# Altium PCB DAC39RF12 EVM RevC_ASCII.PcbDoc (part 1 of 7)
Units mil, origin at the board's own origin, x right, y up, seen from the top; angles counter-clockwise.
Board outline 5071.81 x 2716.54 mil, 16 copper layers (Top Layer, L2 GND1, L3 PWR1, L4 GND2, L5 PWR2, L6 GND3, L7 Ctrl Signal 1, L8 GND4, L9 GND5, L10 Ctrl Signal 2, L11 GND6, L12 PWR3, L13 GND7, L14 PWR4, L15 GND8, Bottom Layer), stack 82.4 mil thick; 596 components, 375 nets, 3310 pads, 1662 vias.
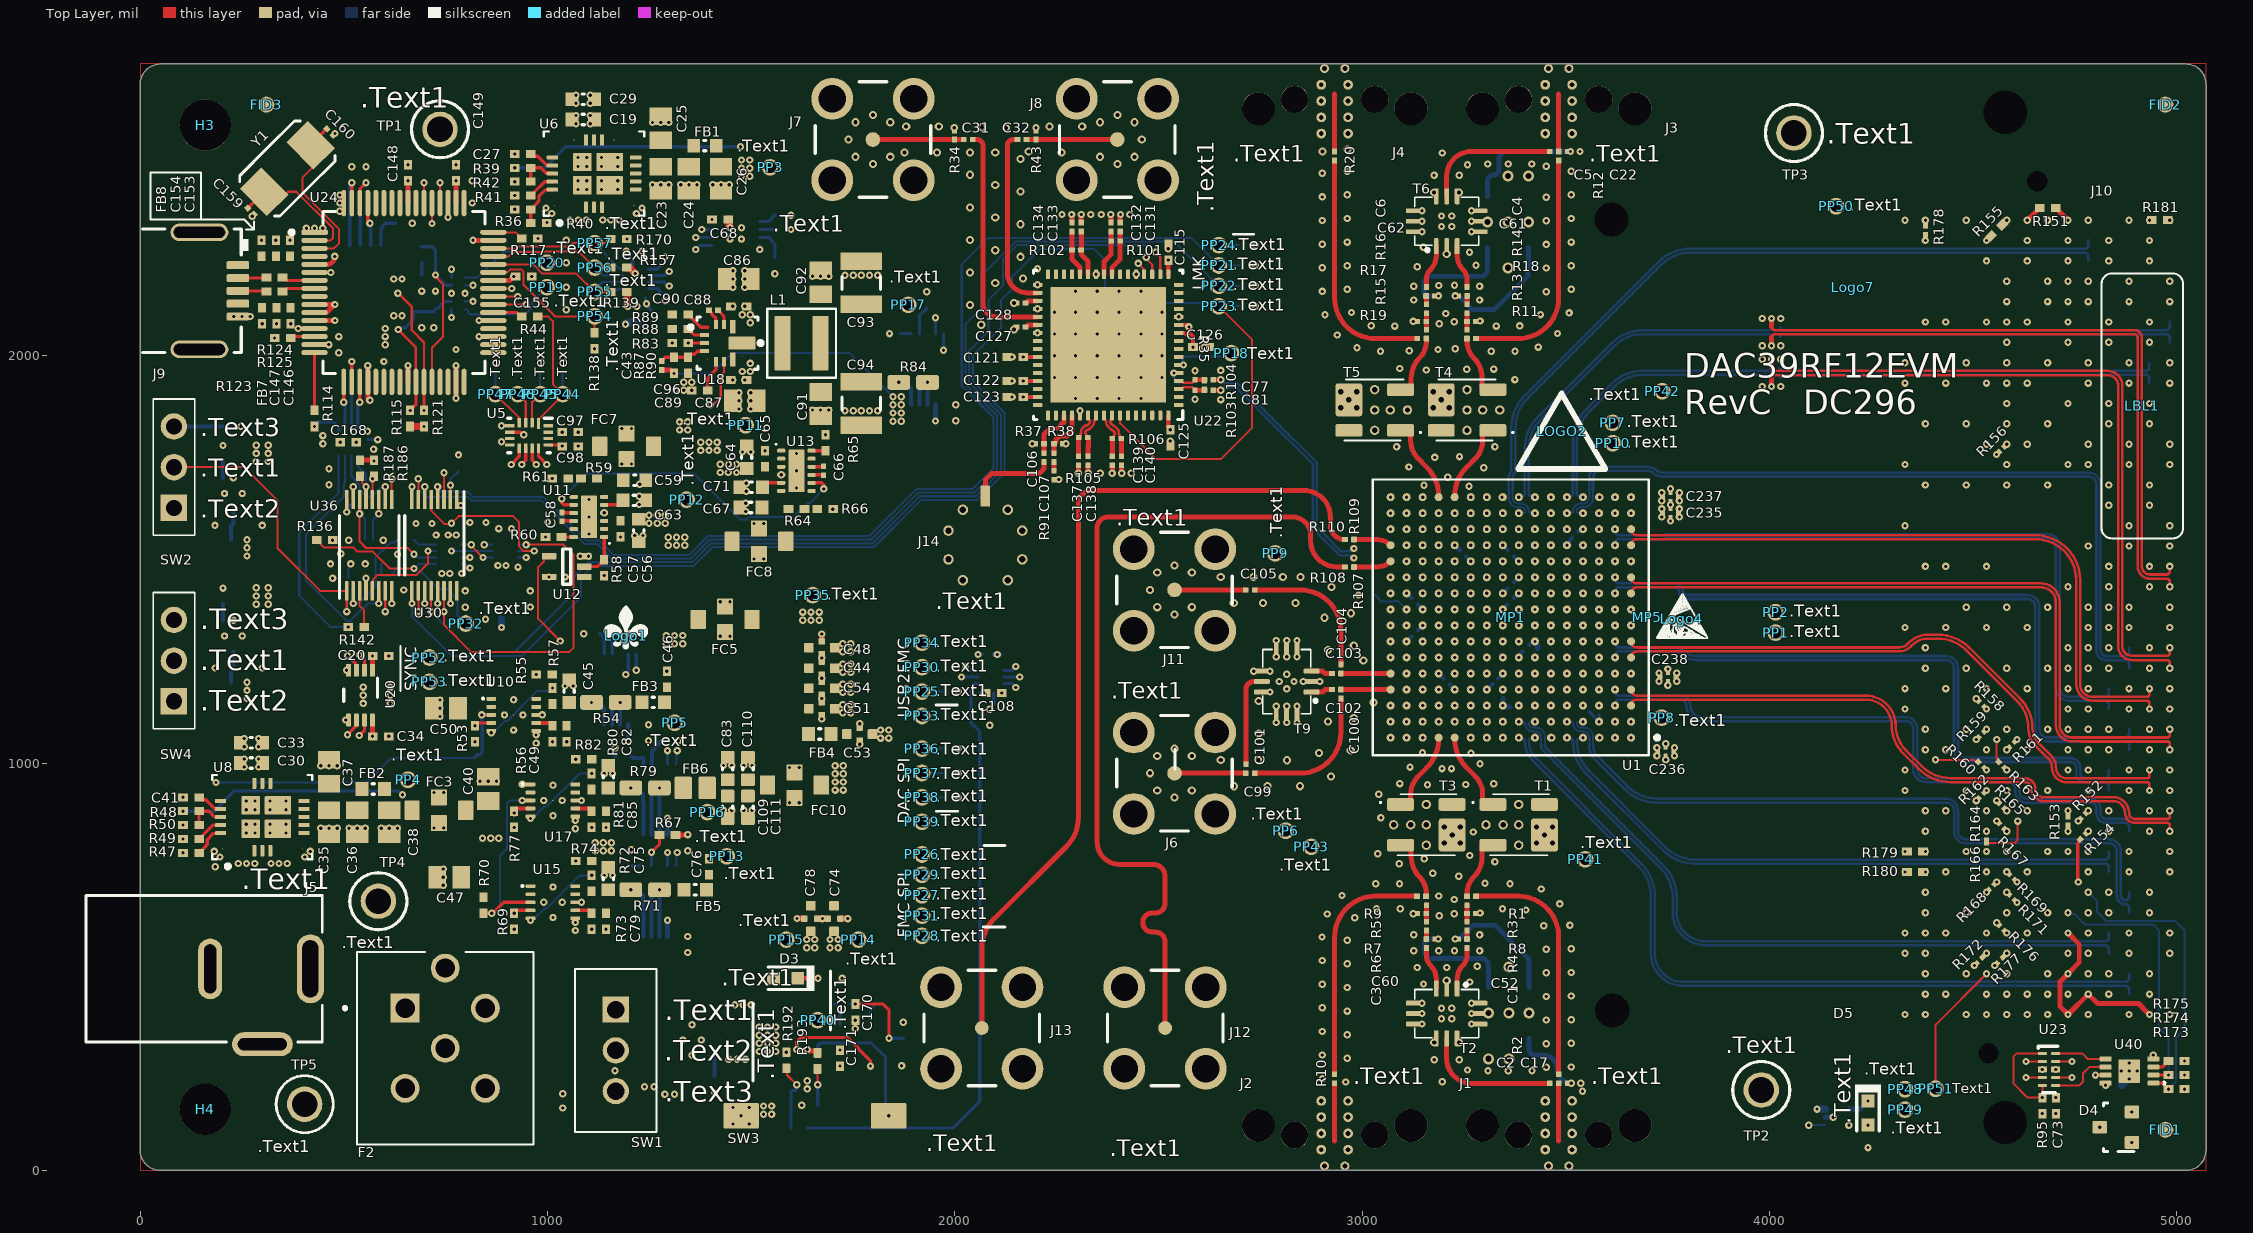
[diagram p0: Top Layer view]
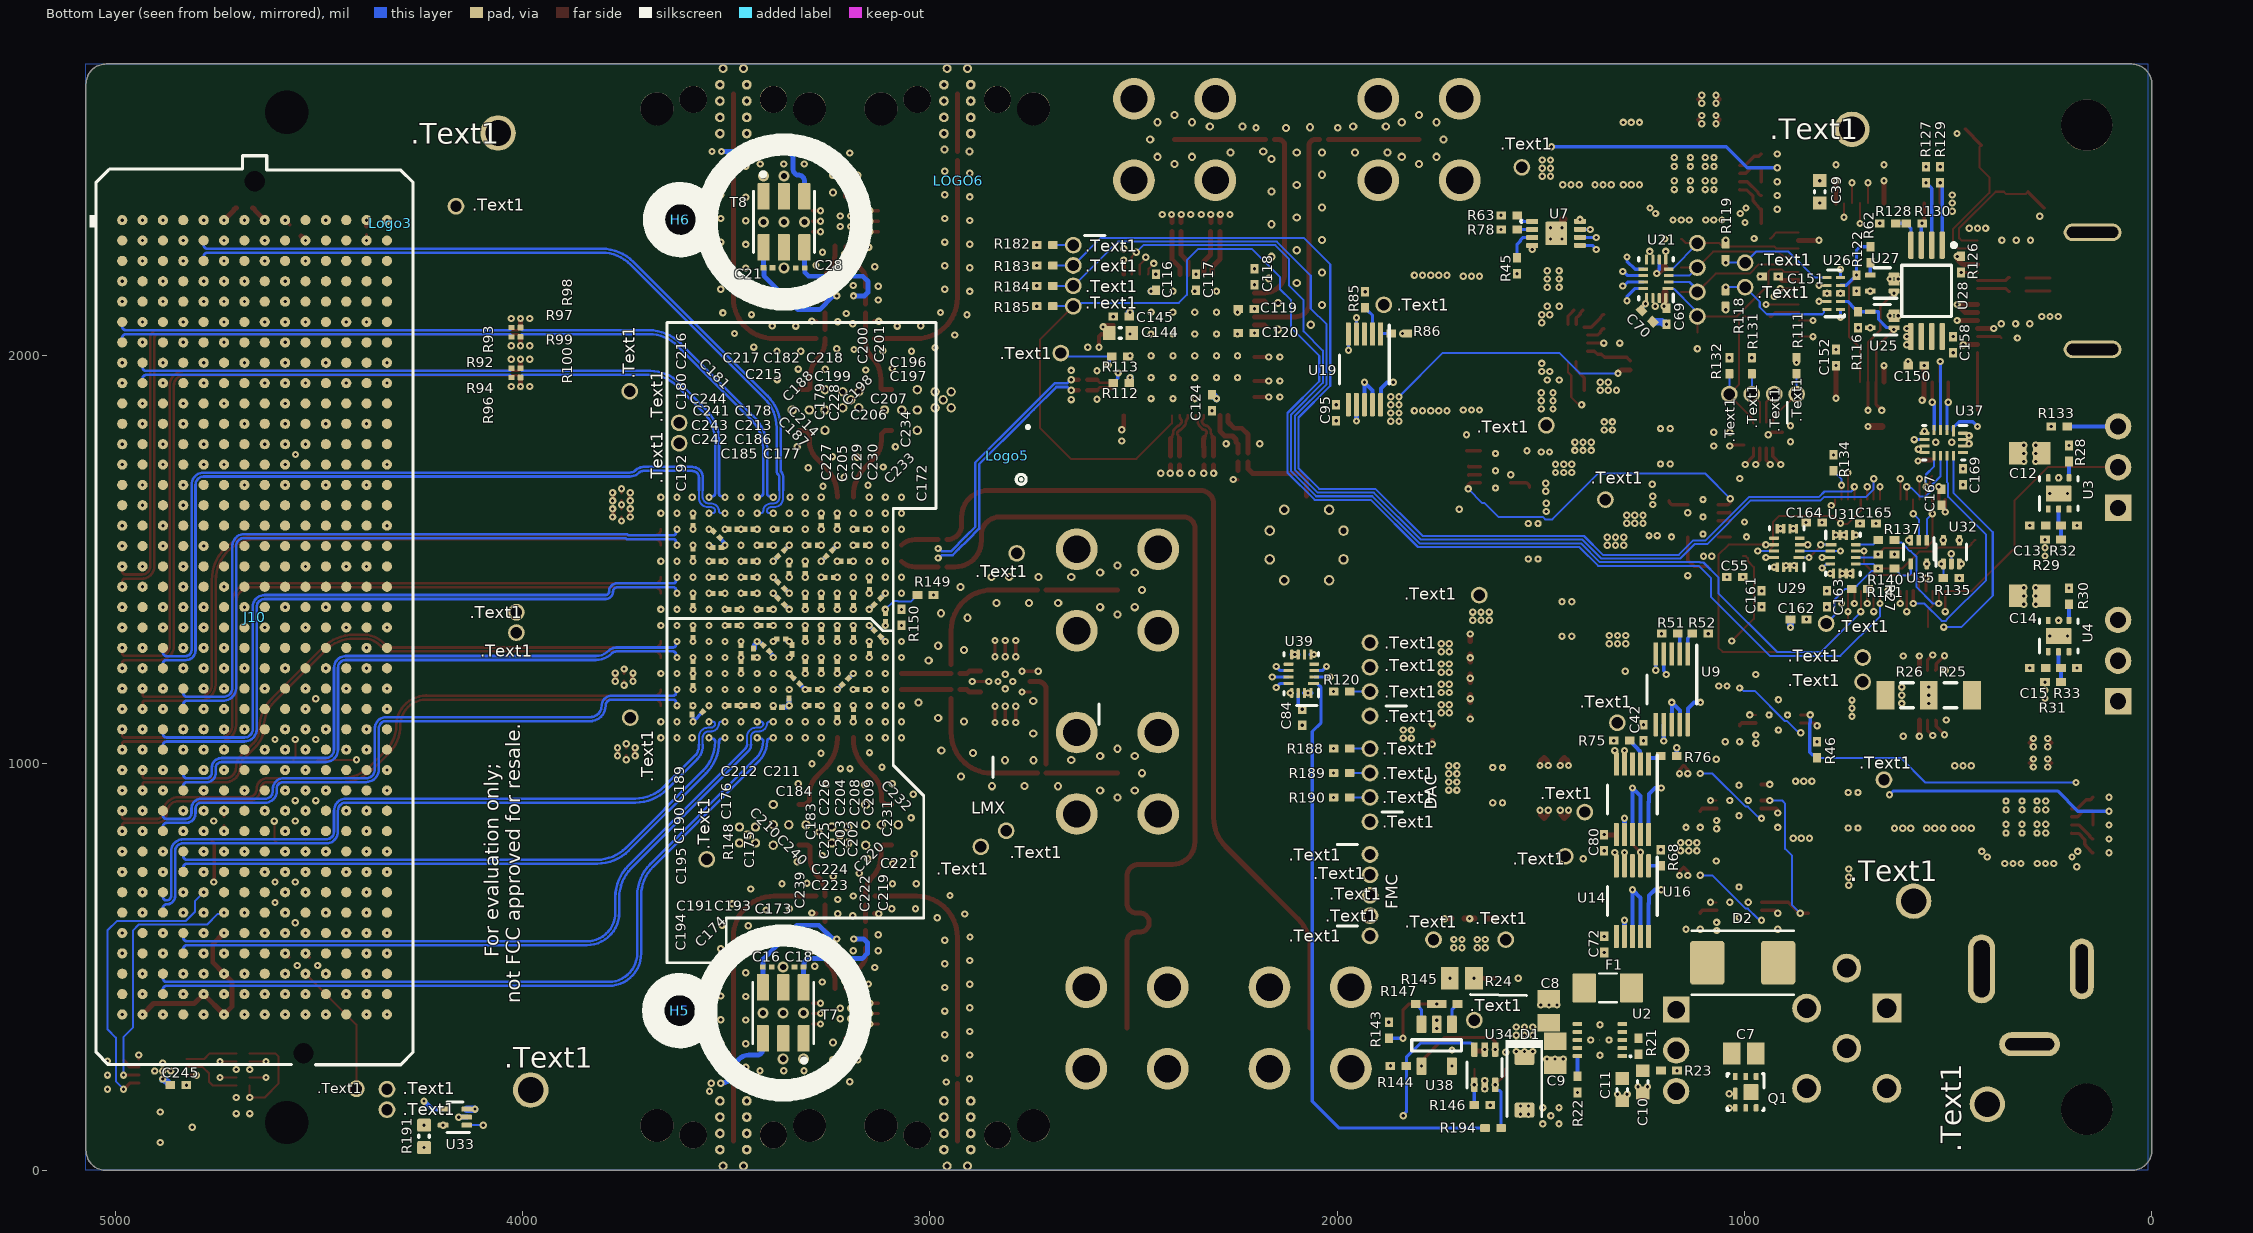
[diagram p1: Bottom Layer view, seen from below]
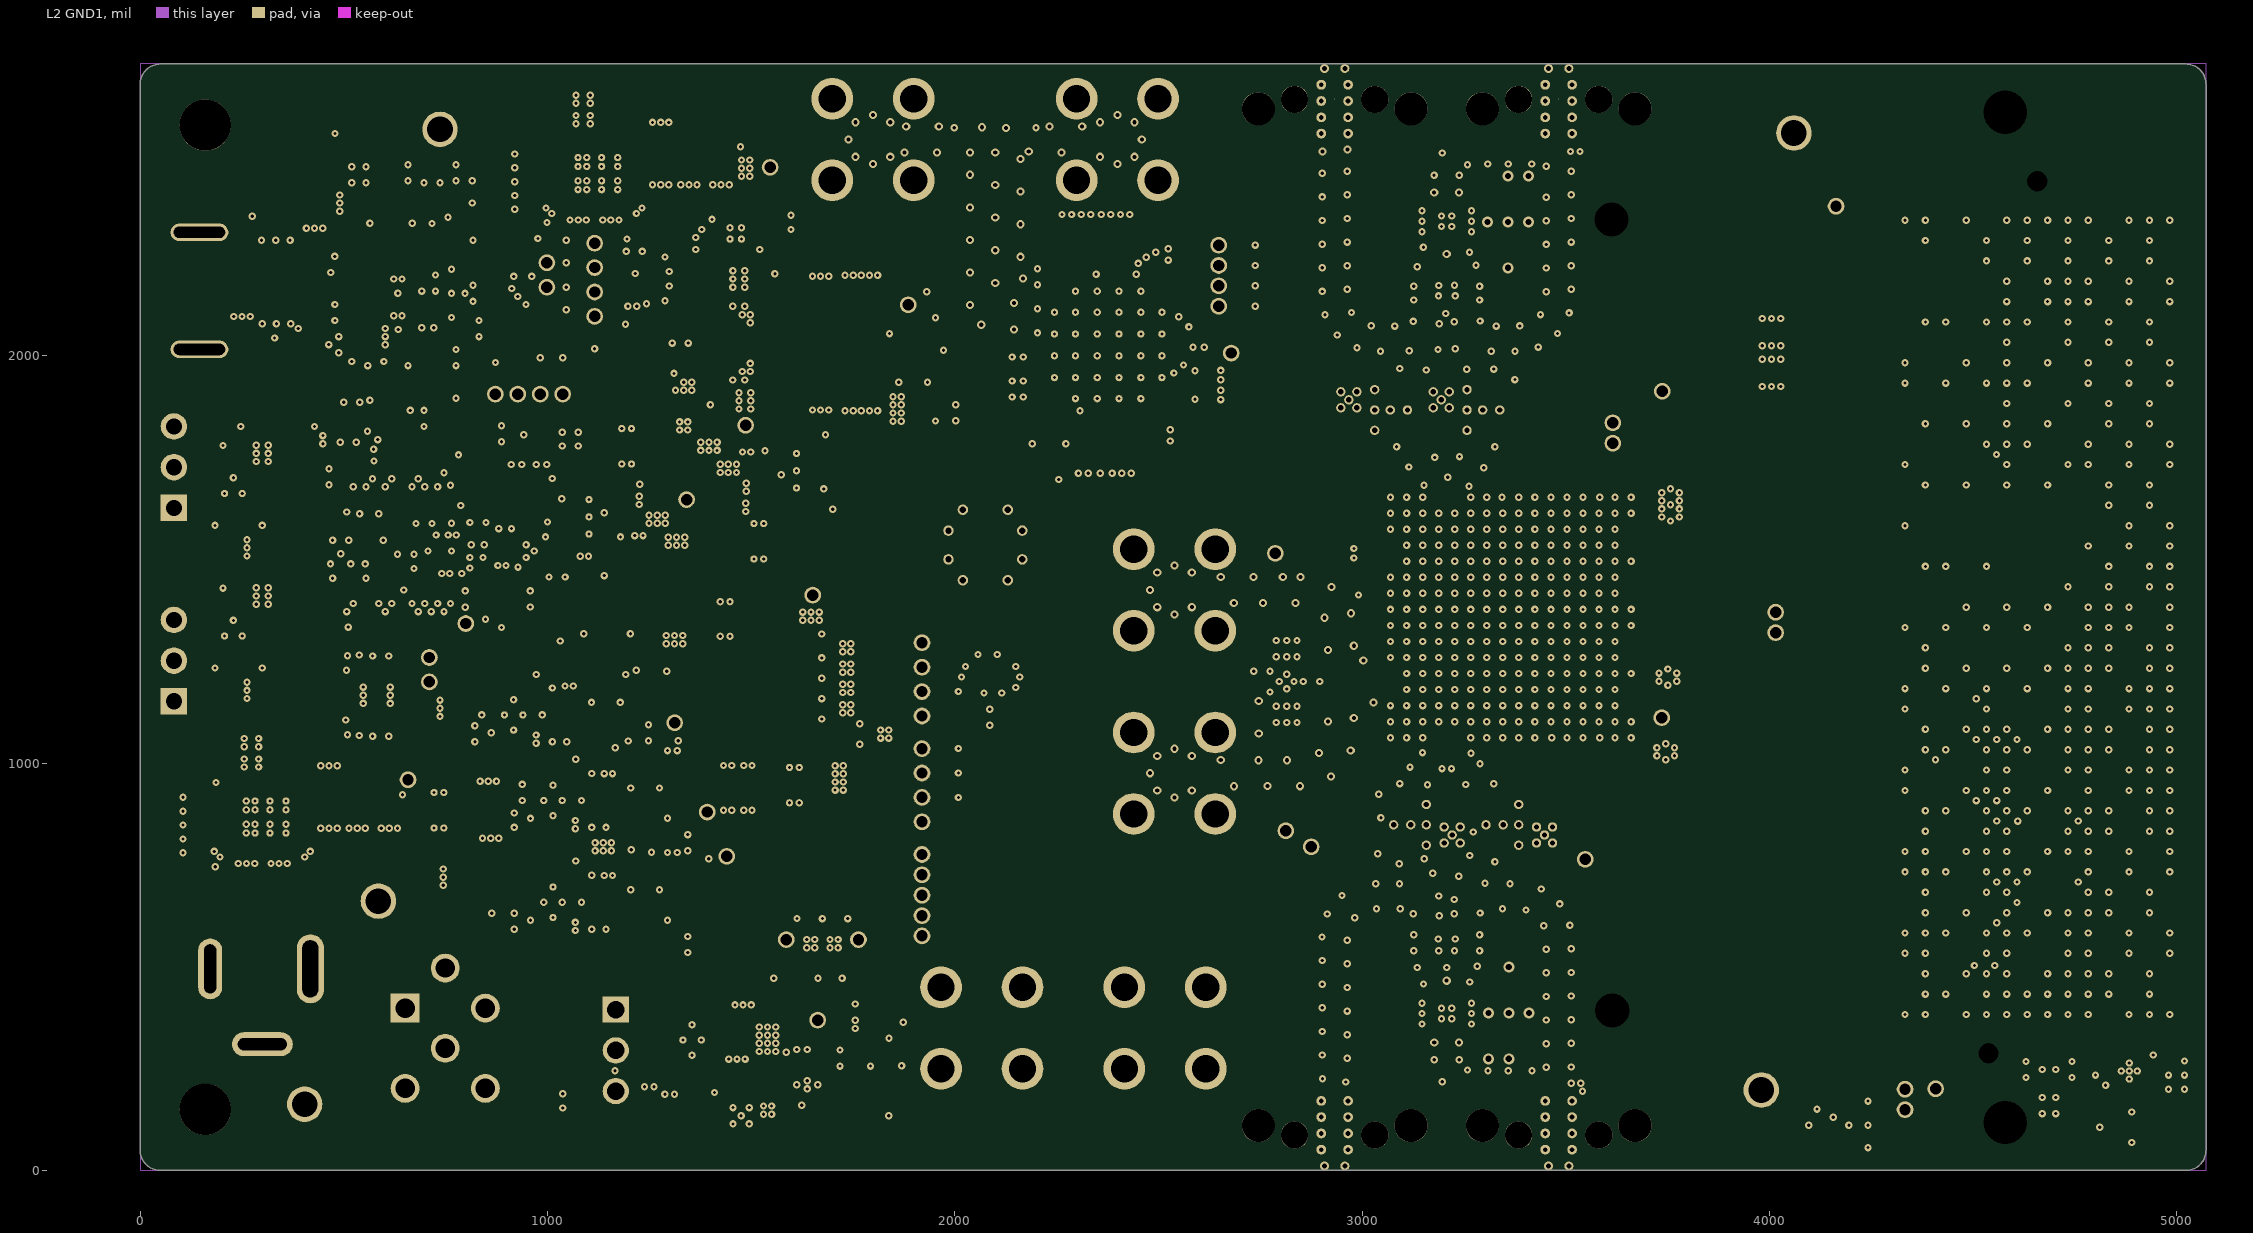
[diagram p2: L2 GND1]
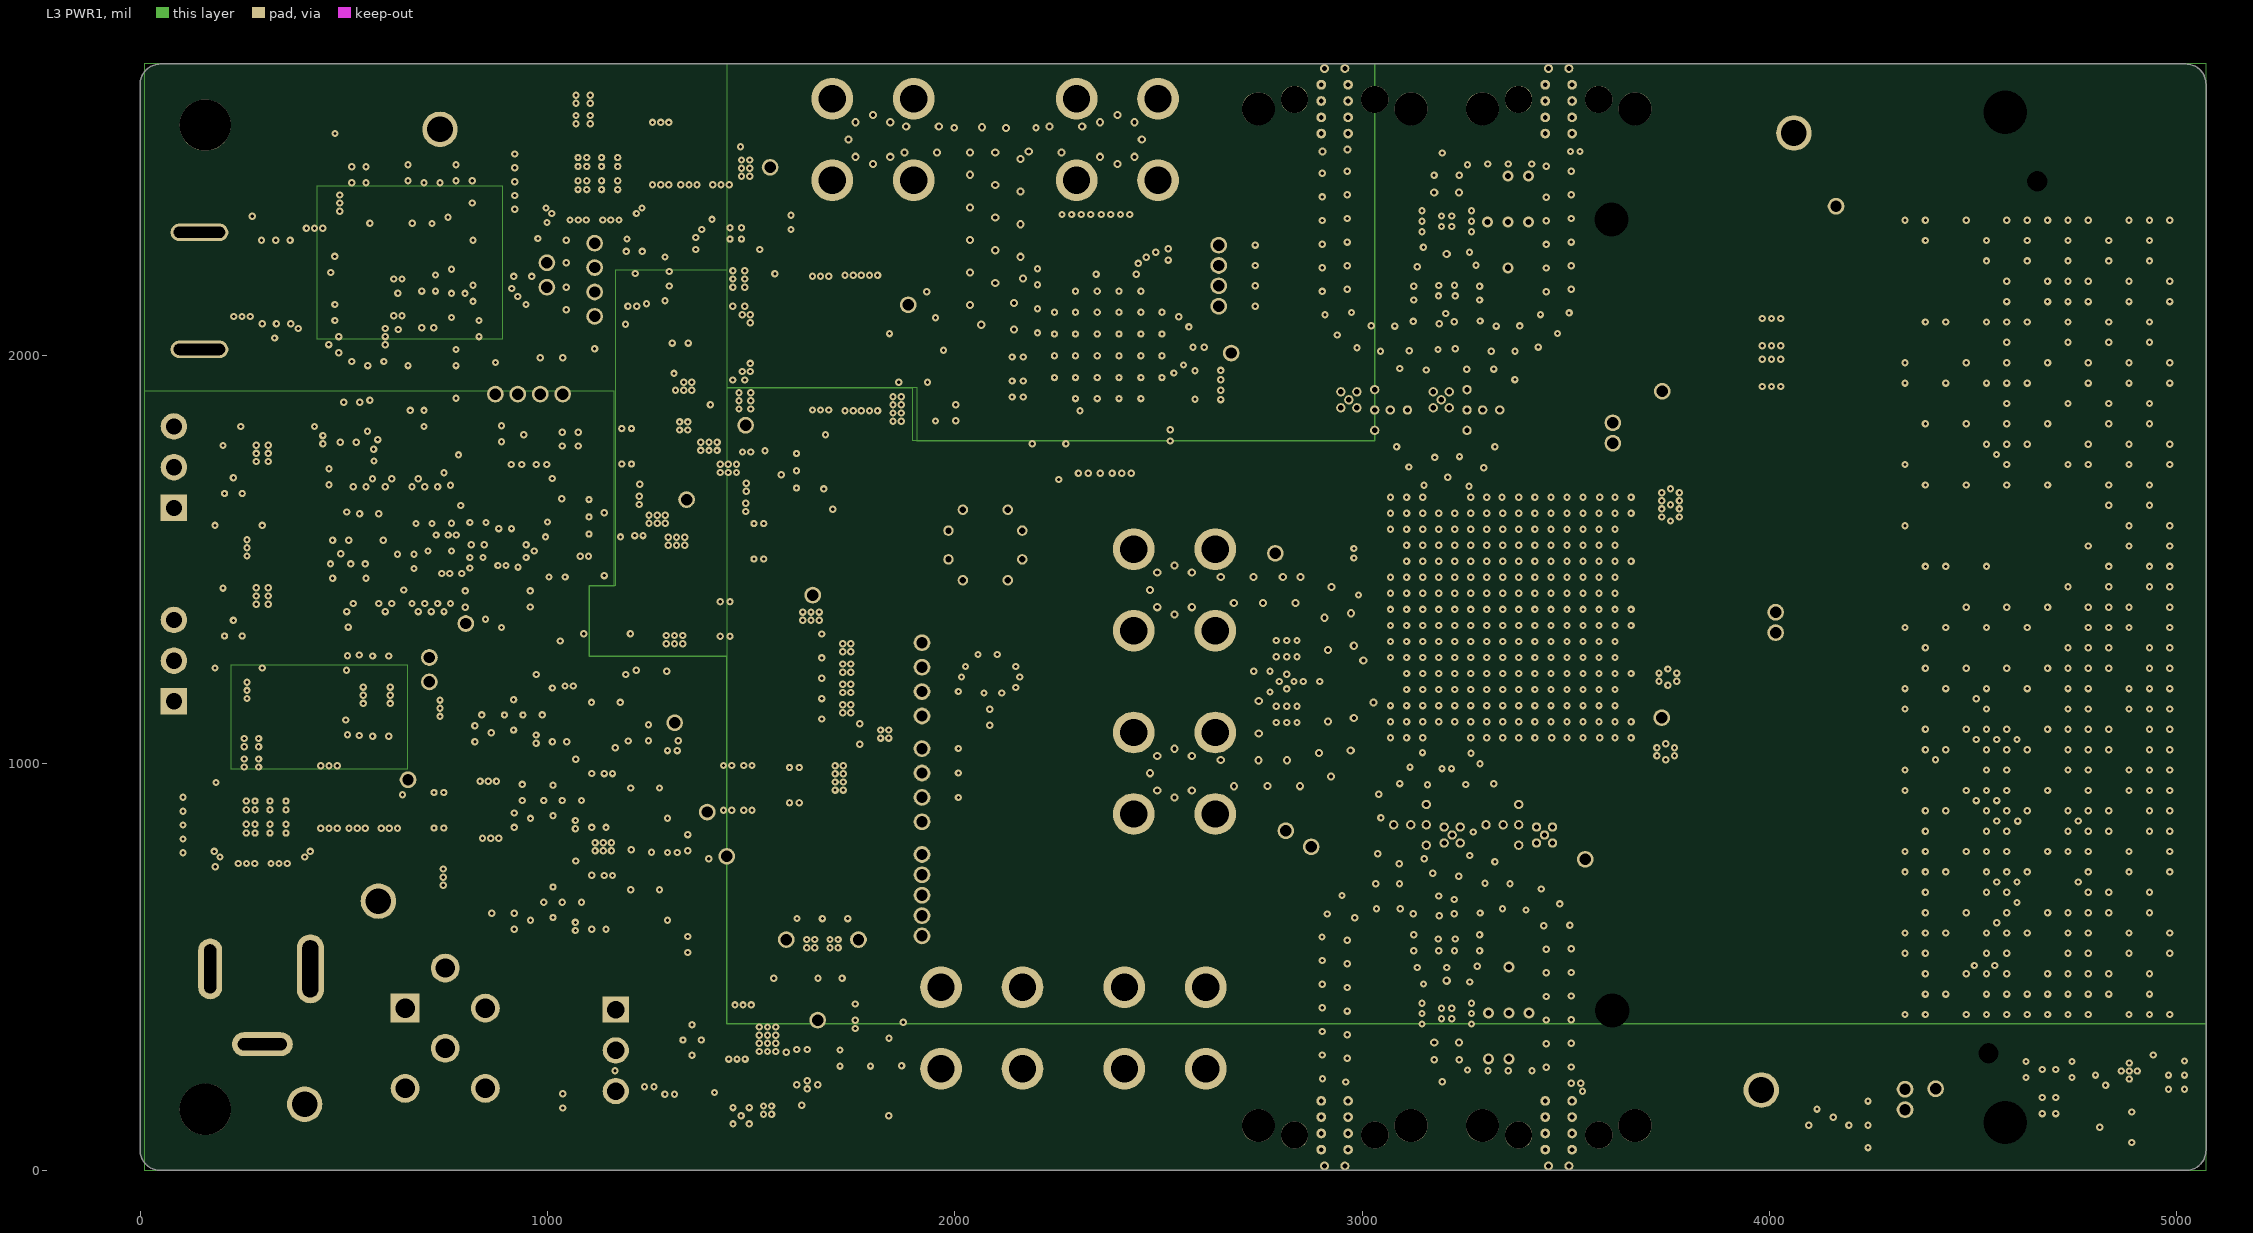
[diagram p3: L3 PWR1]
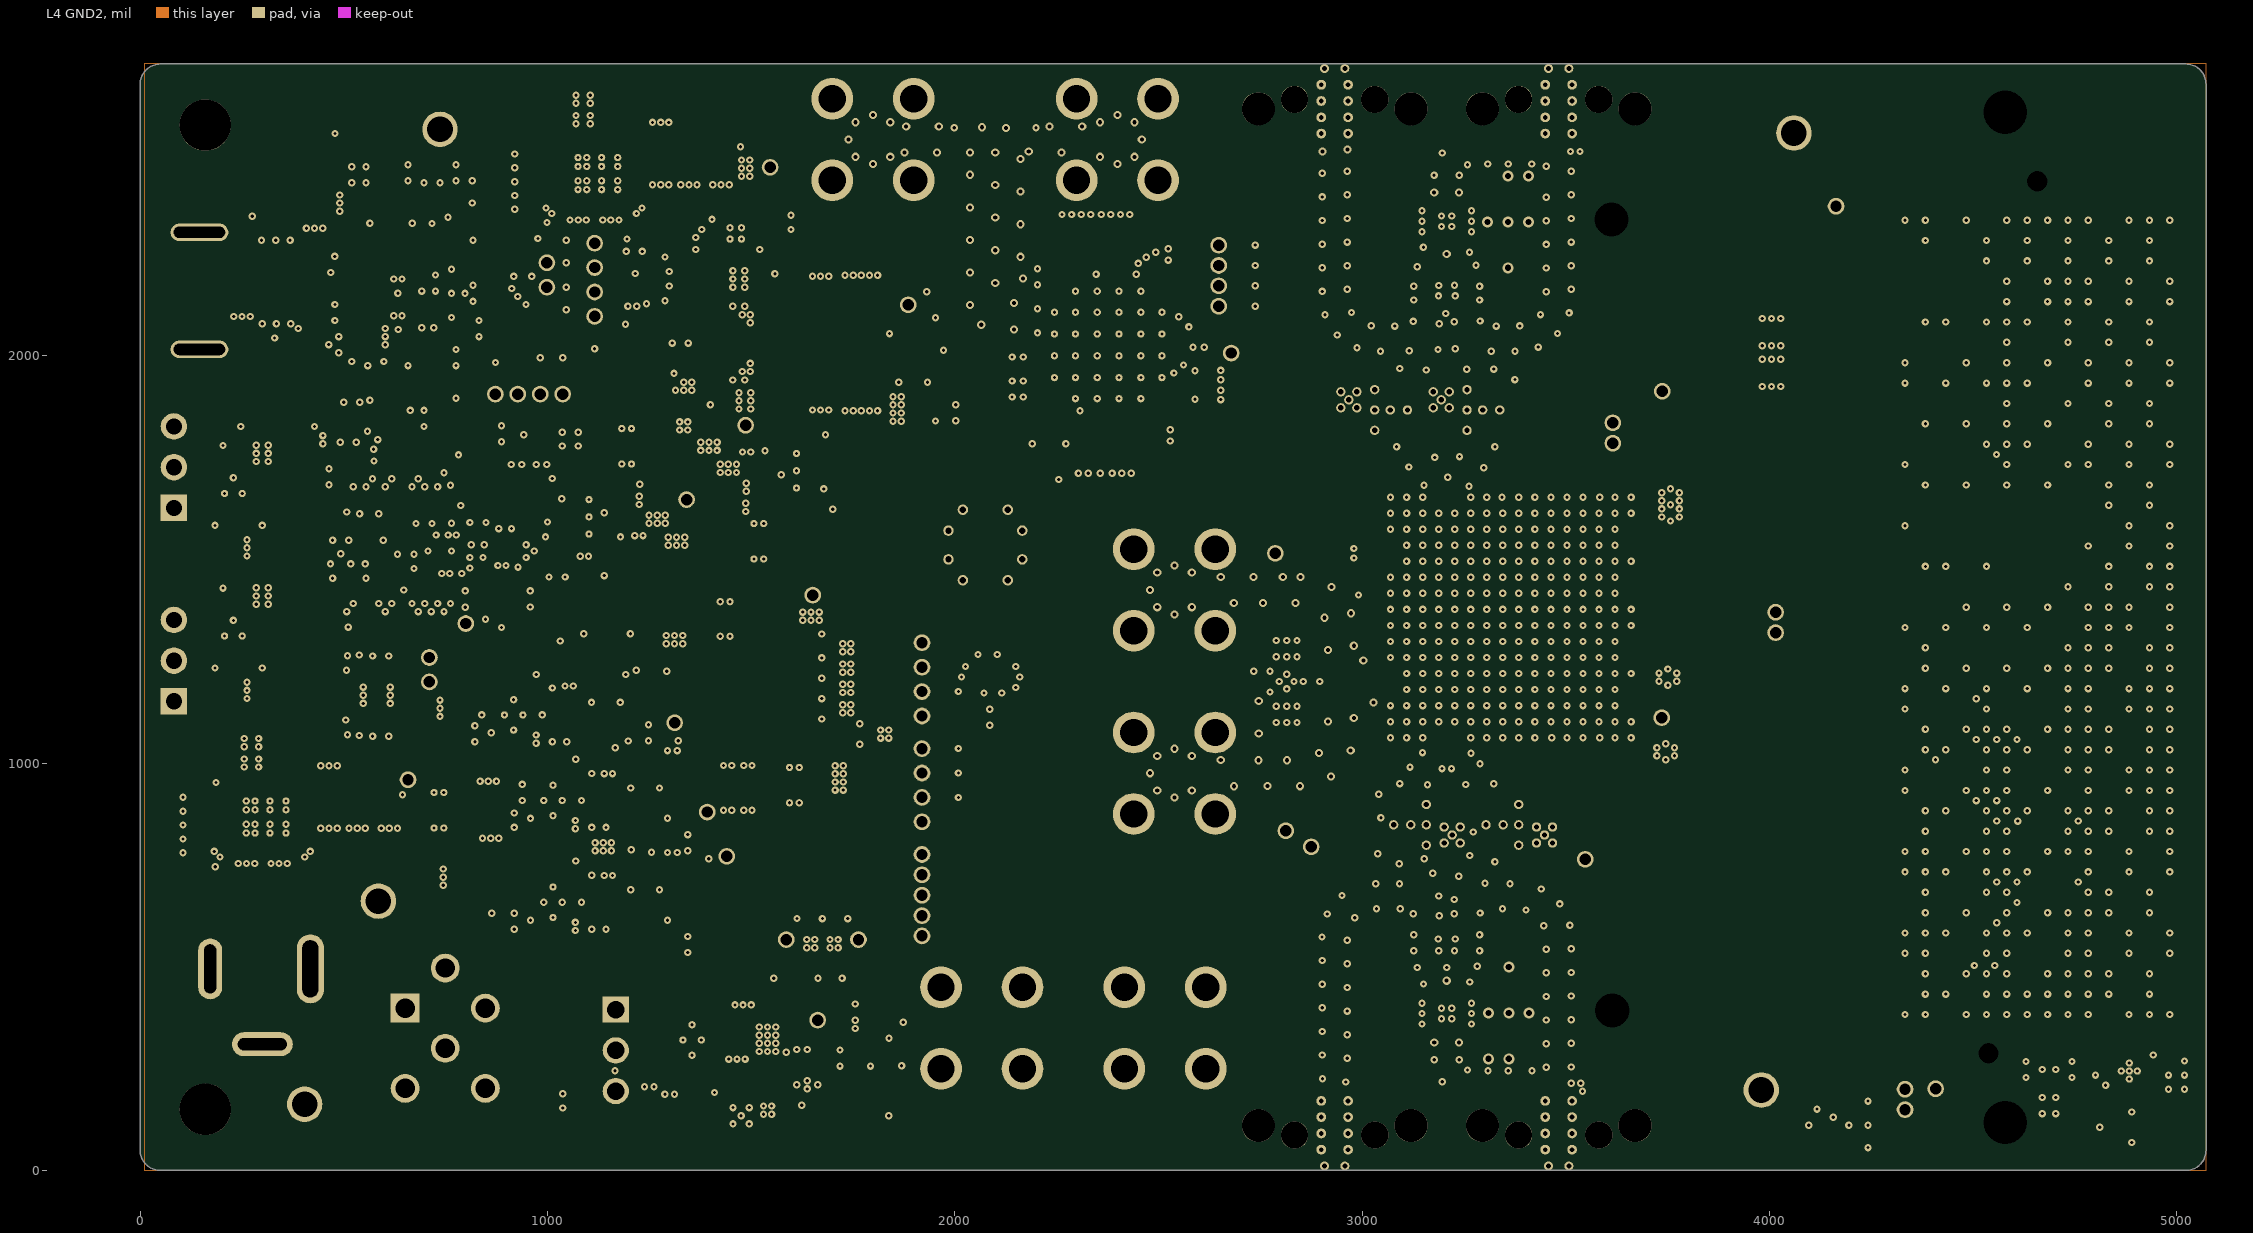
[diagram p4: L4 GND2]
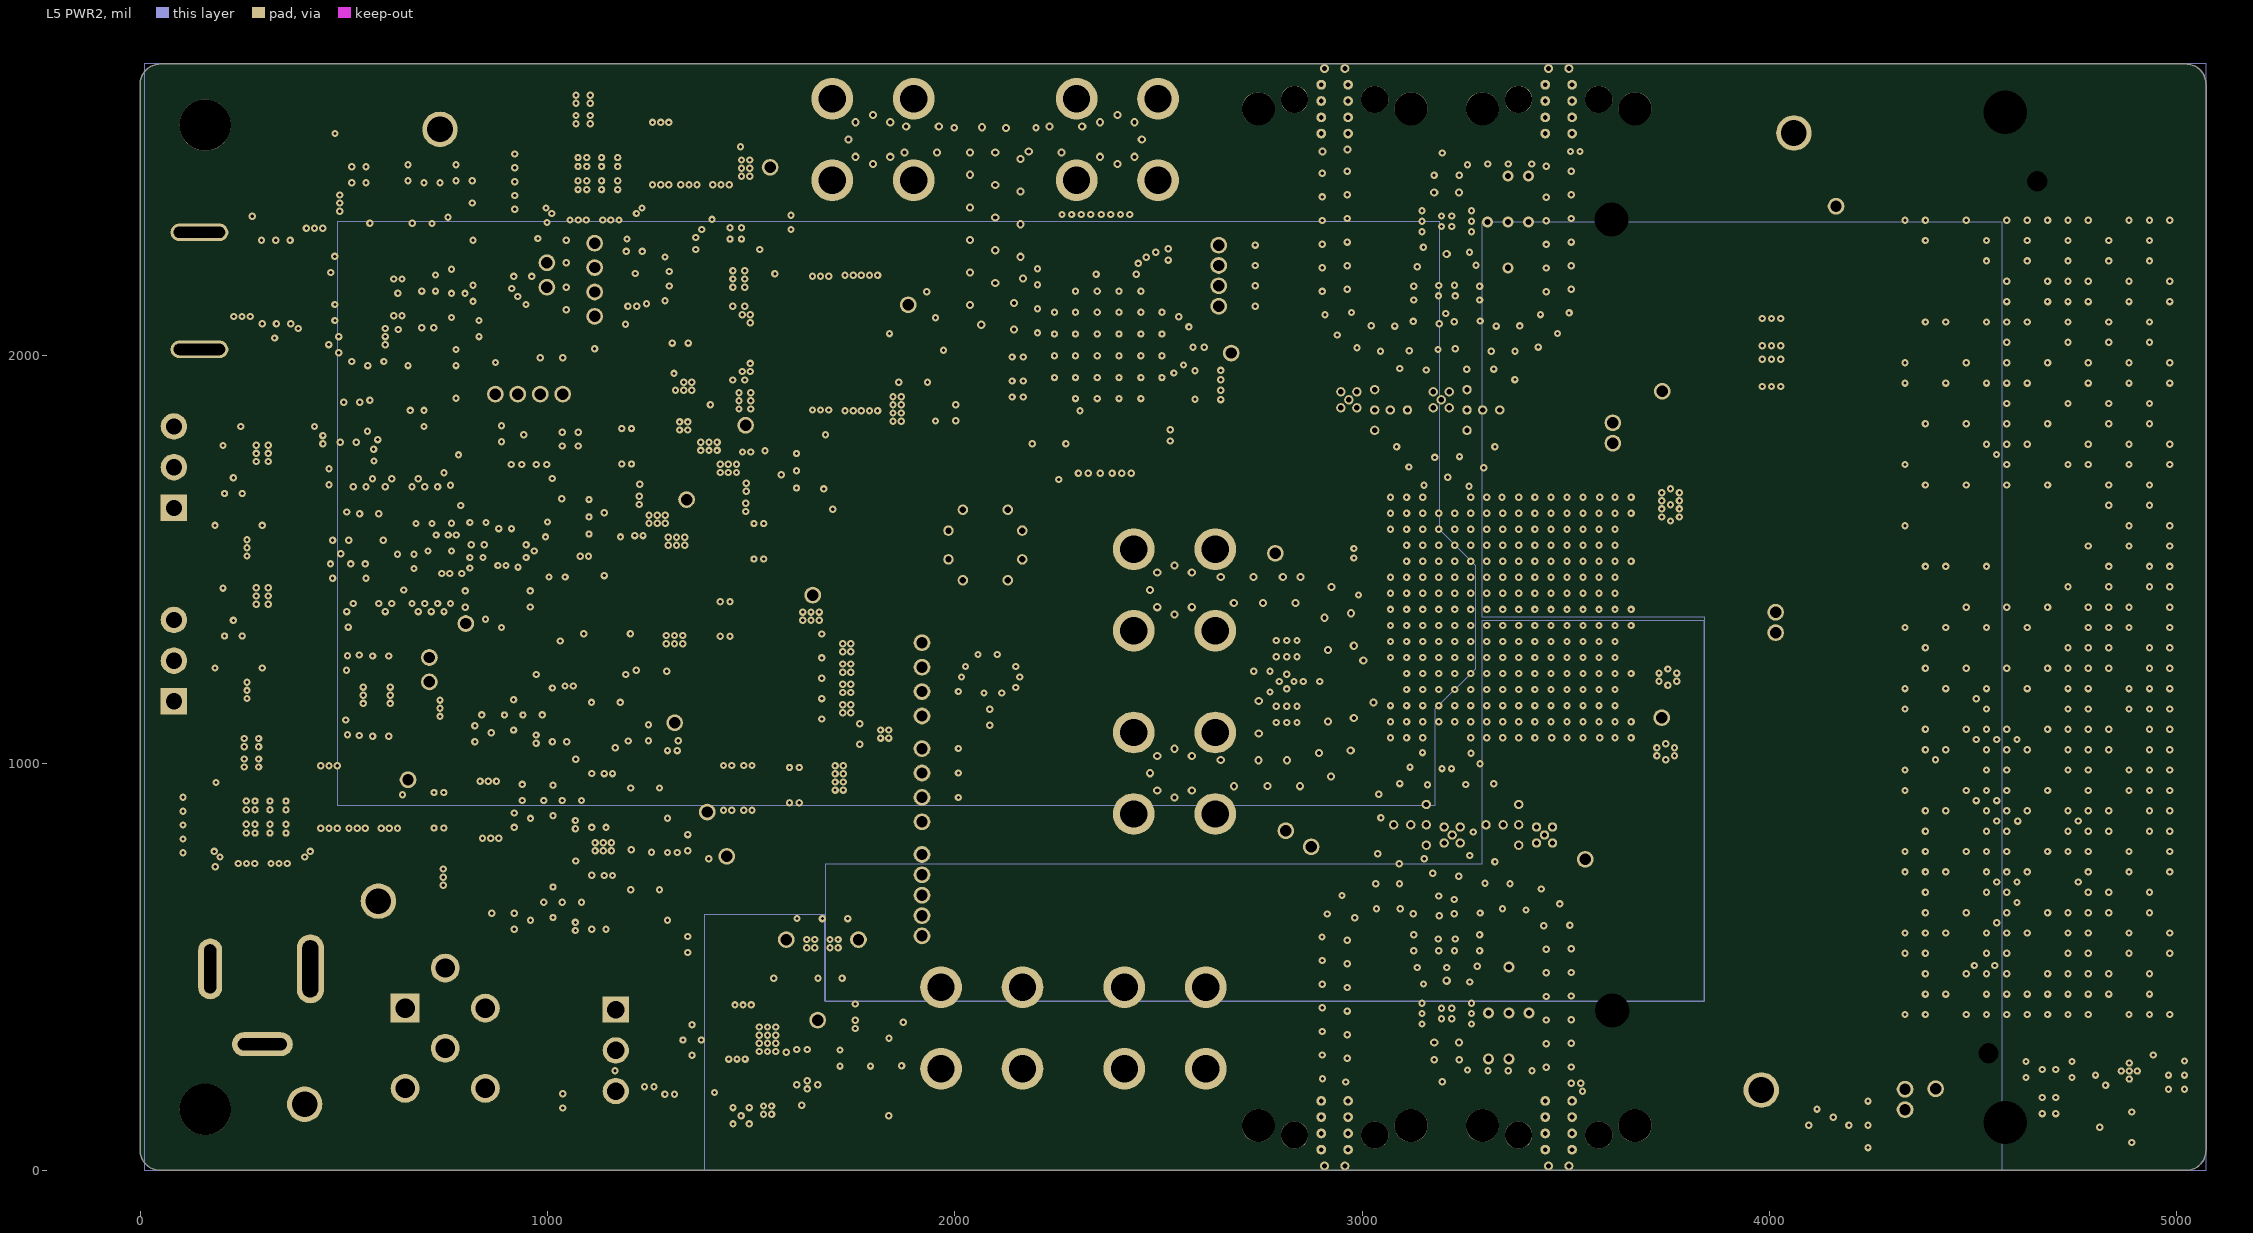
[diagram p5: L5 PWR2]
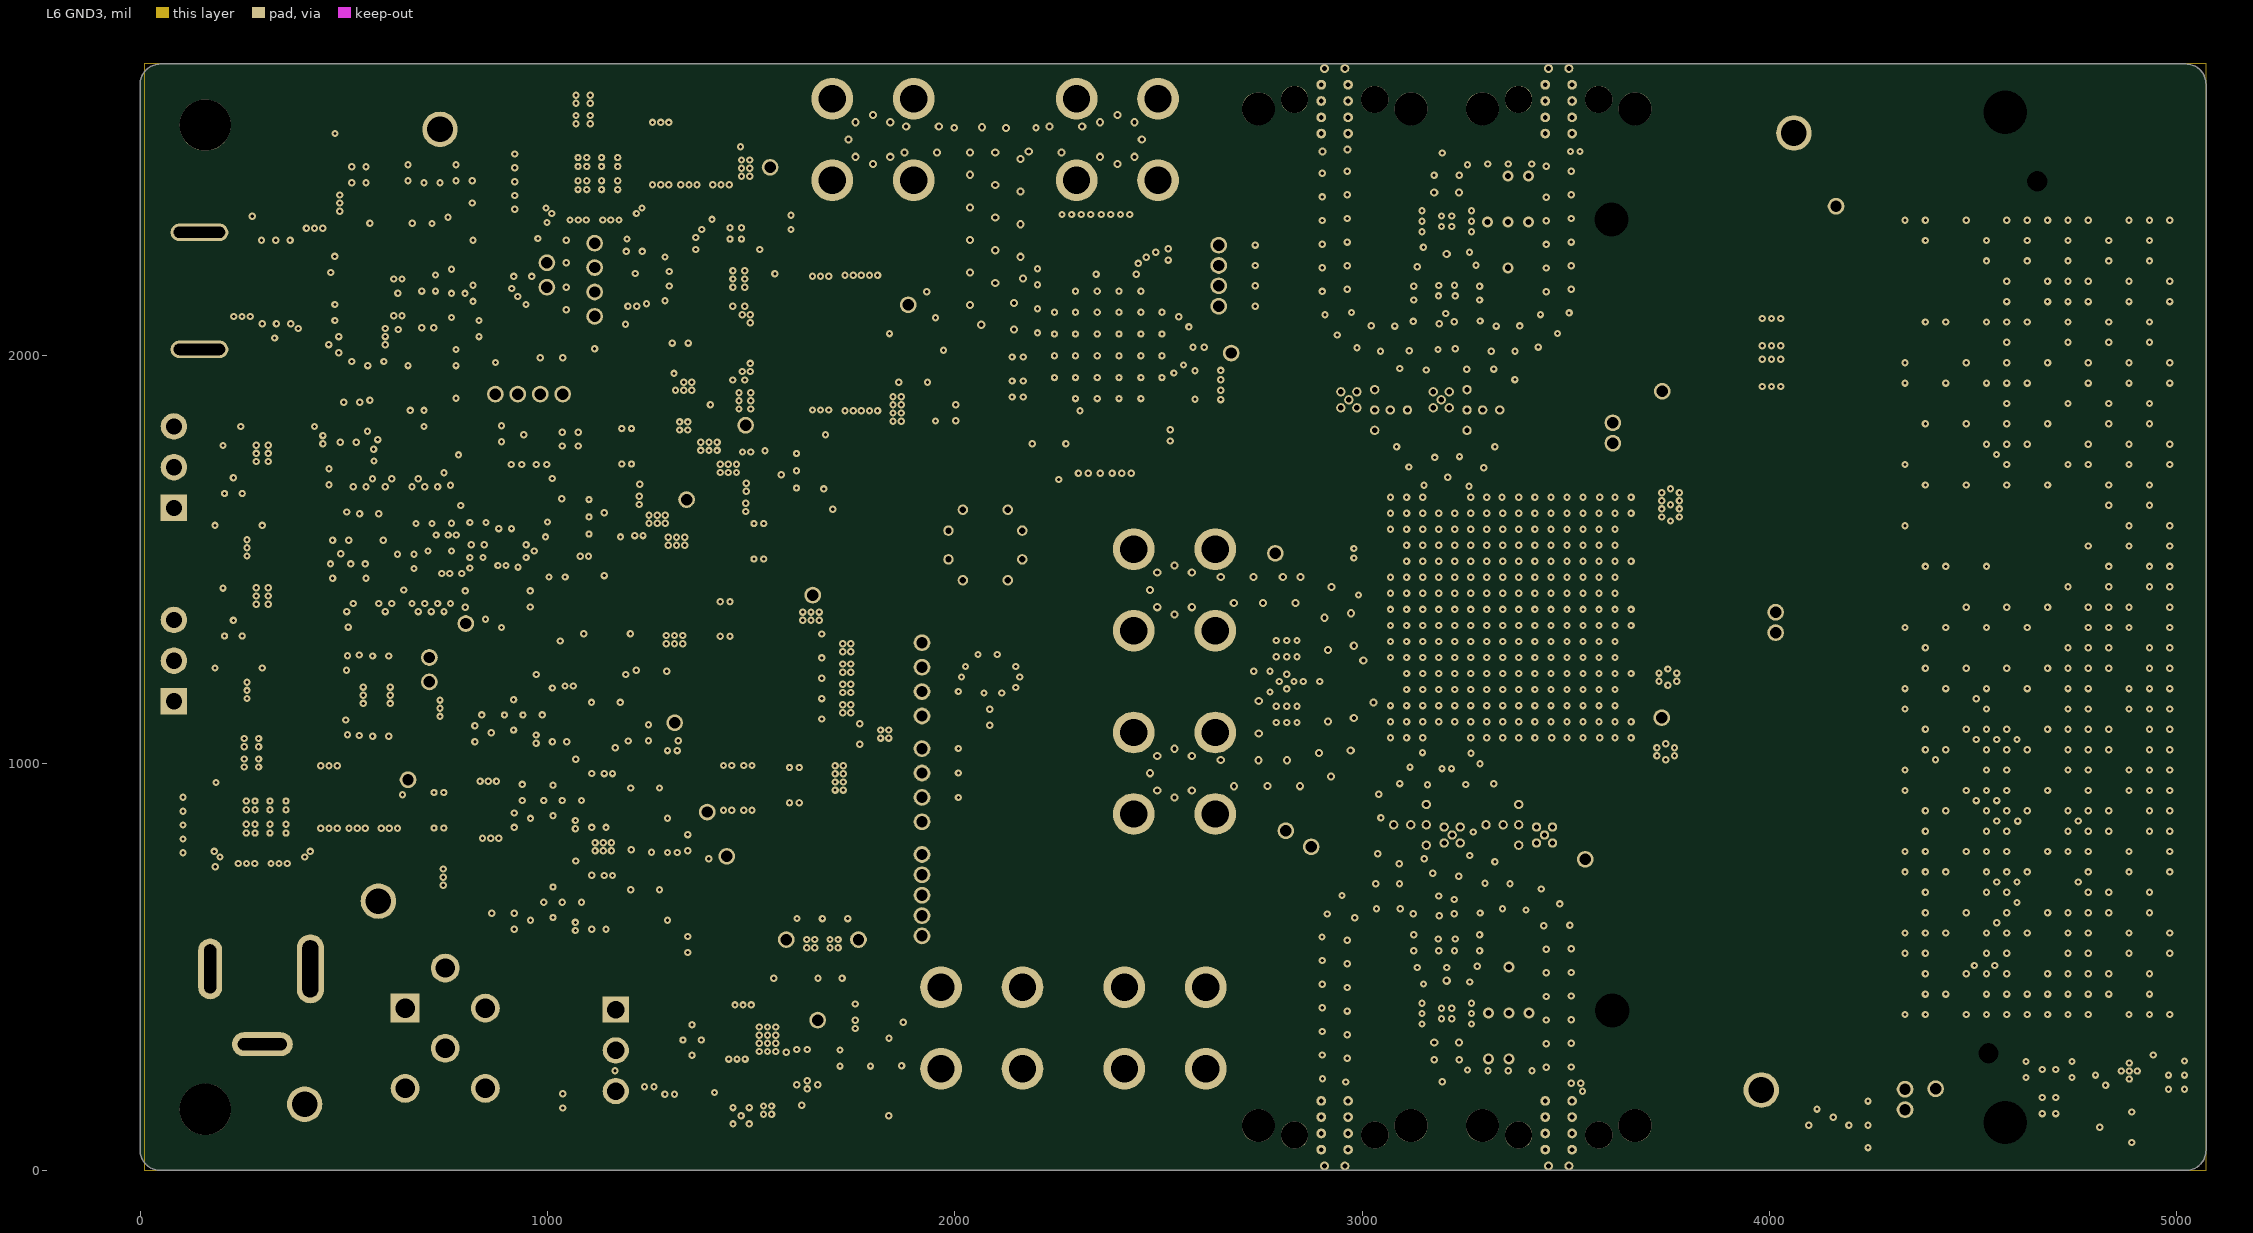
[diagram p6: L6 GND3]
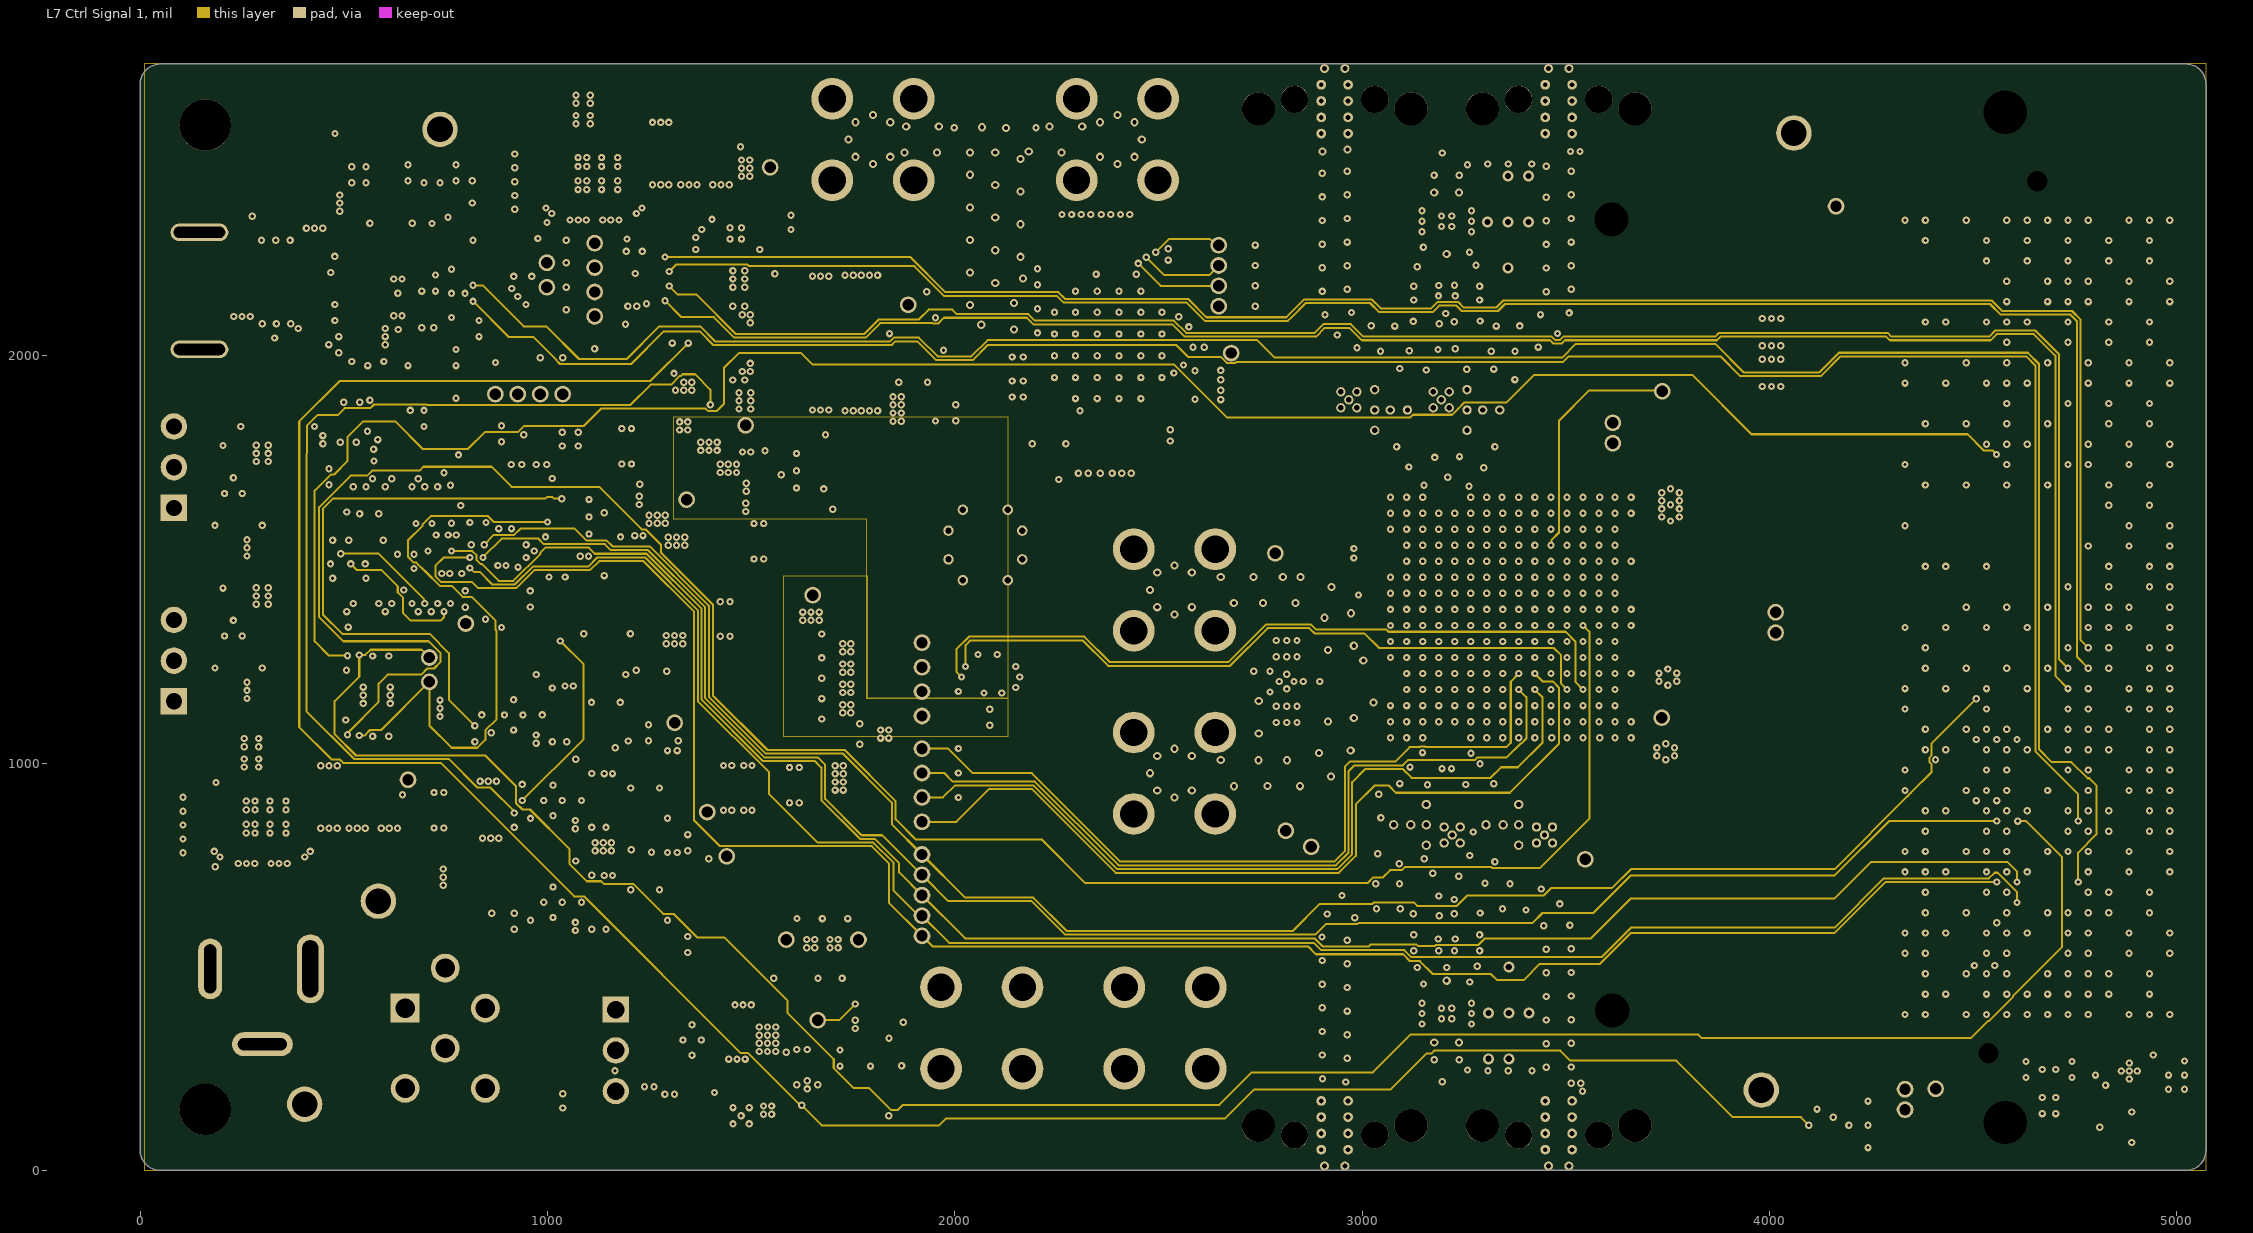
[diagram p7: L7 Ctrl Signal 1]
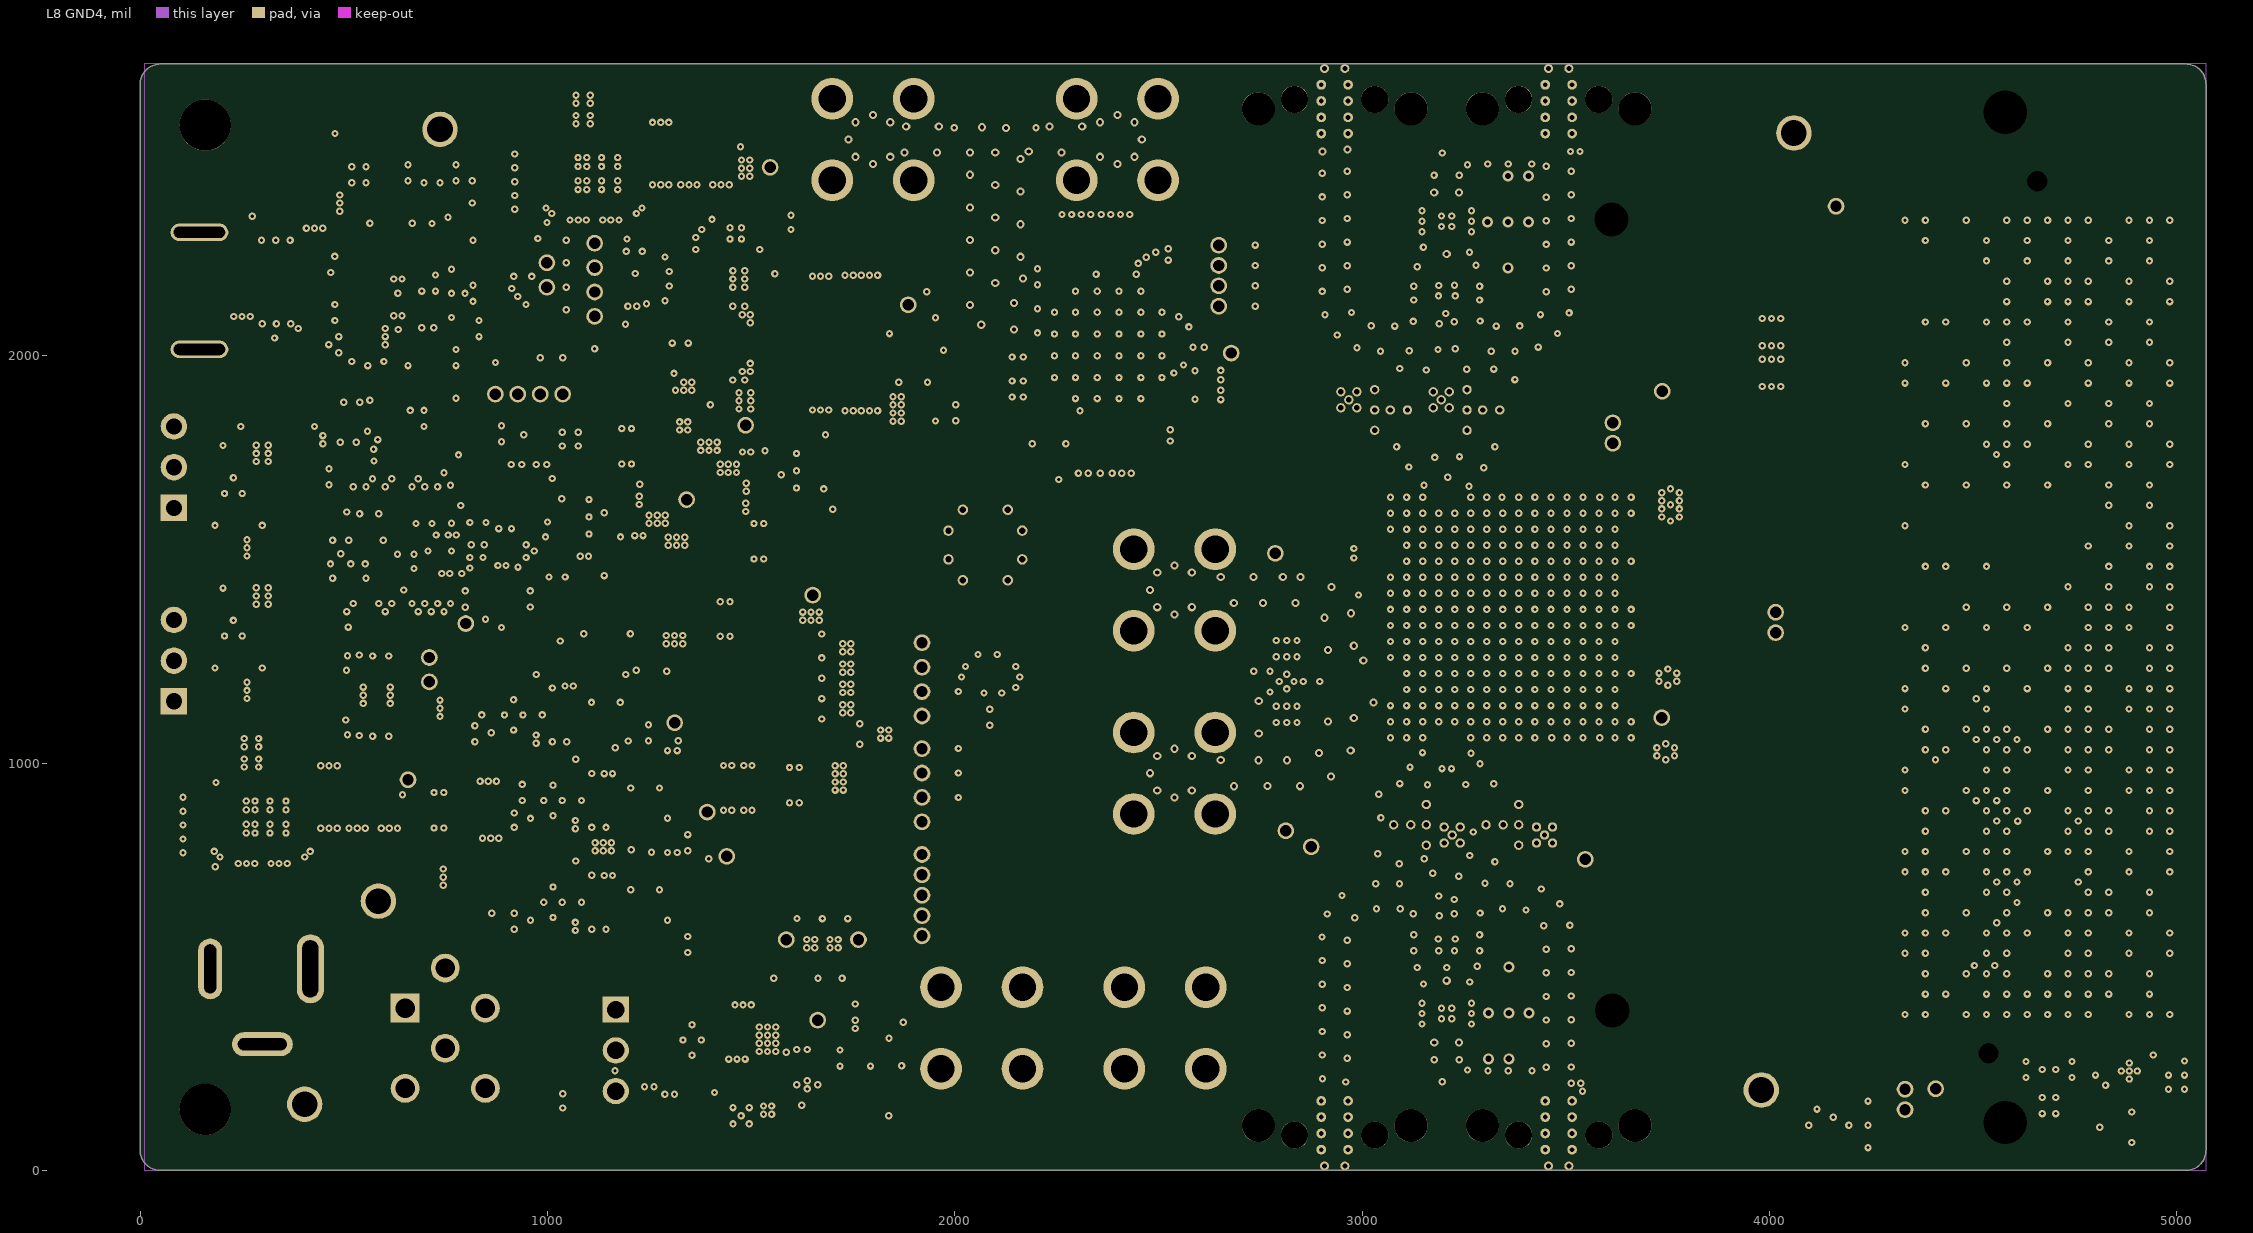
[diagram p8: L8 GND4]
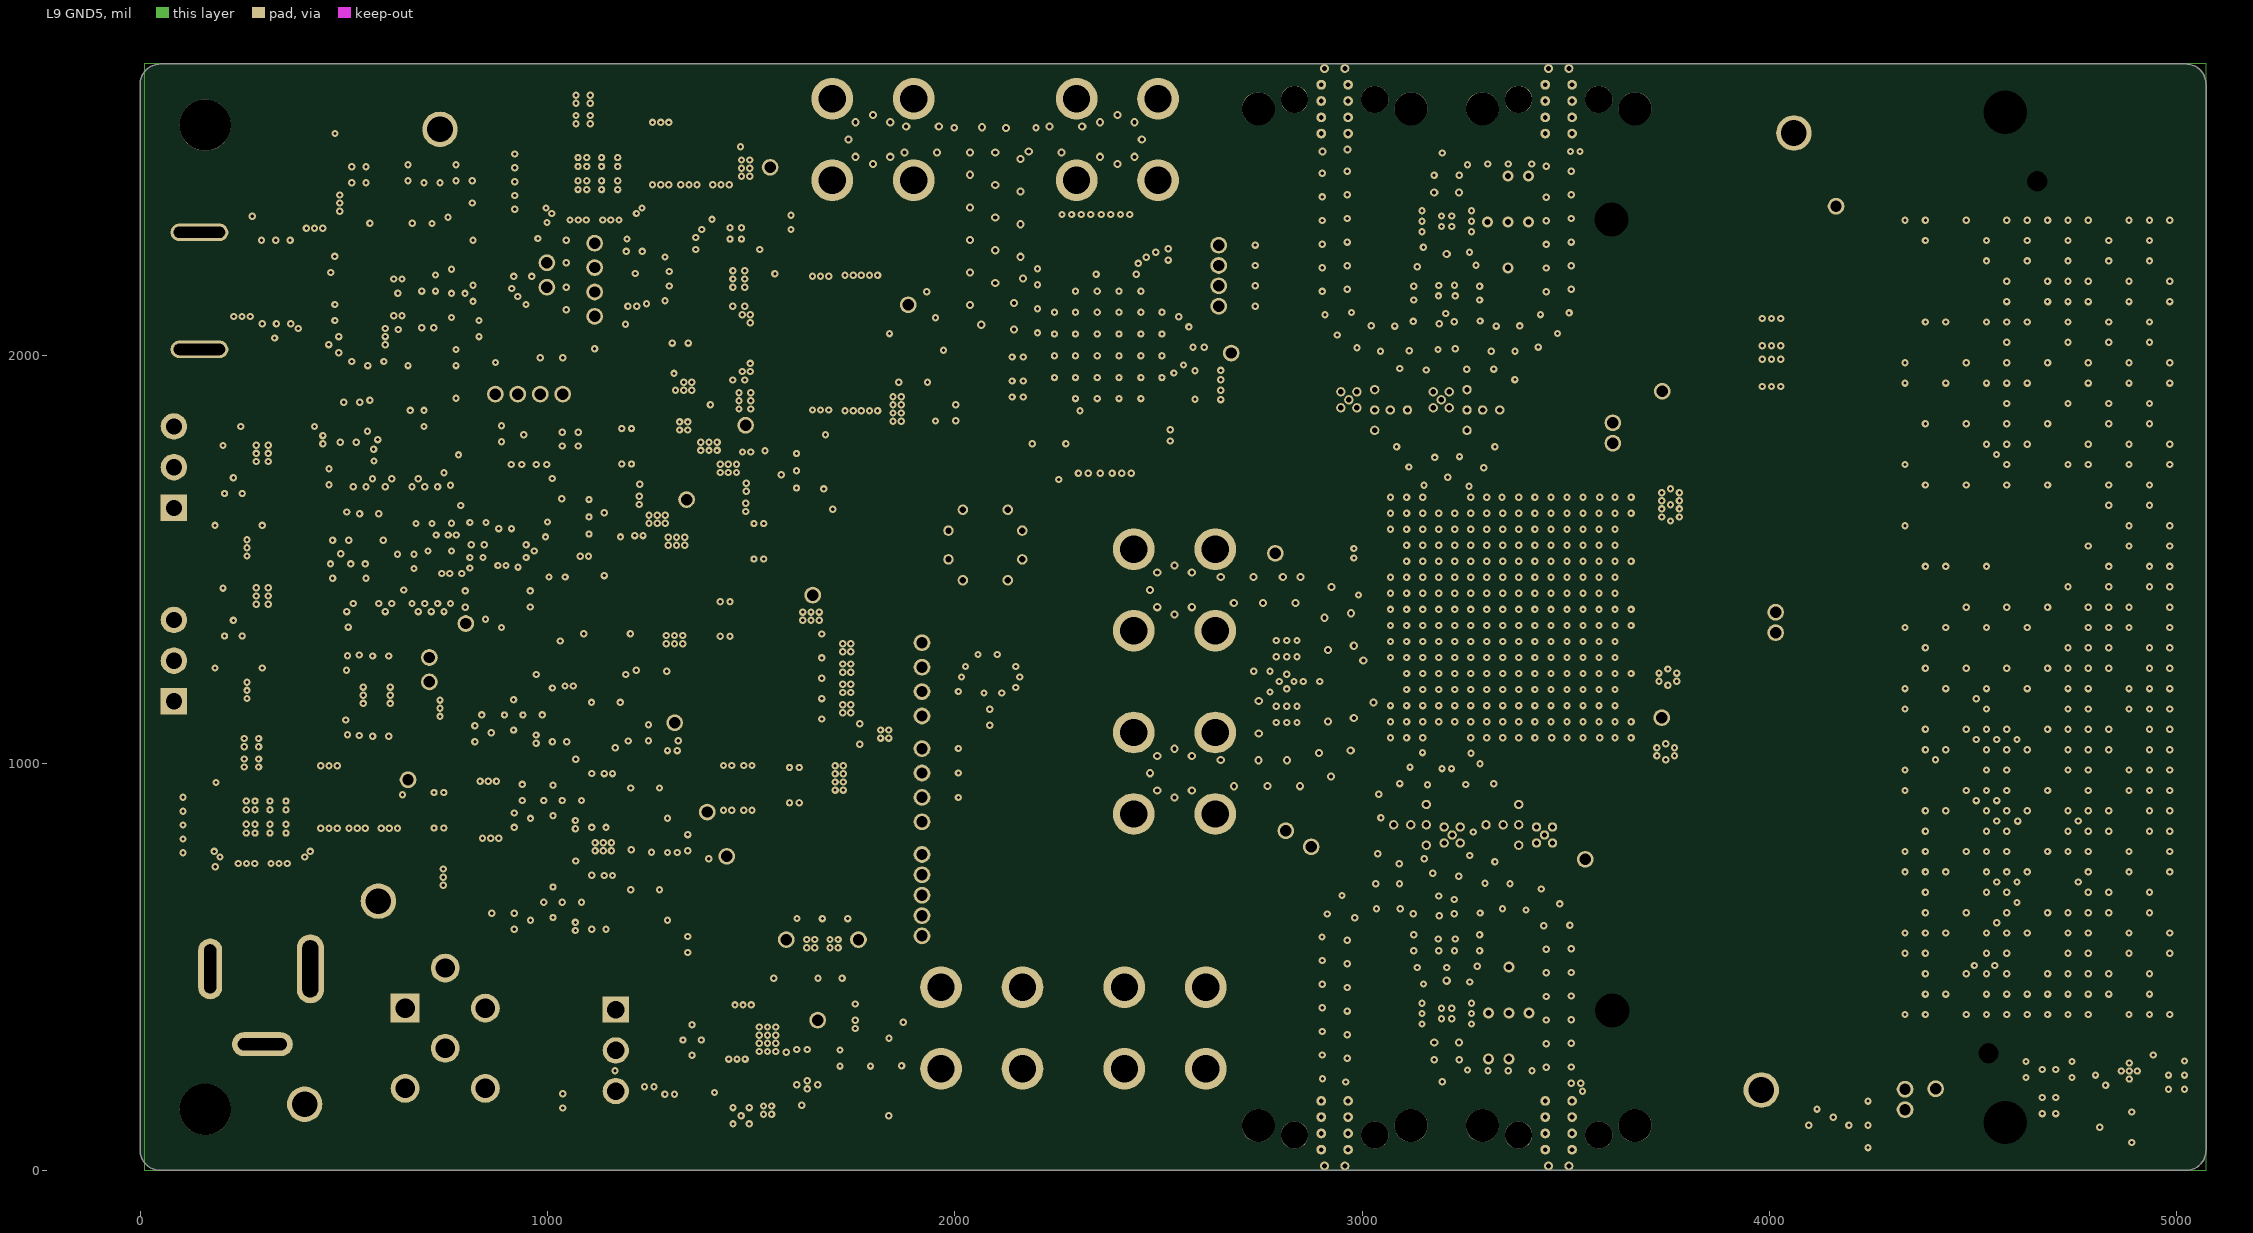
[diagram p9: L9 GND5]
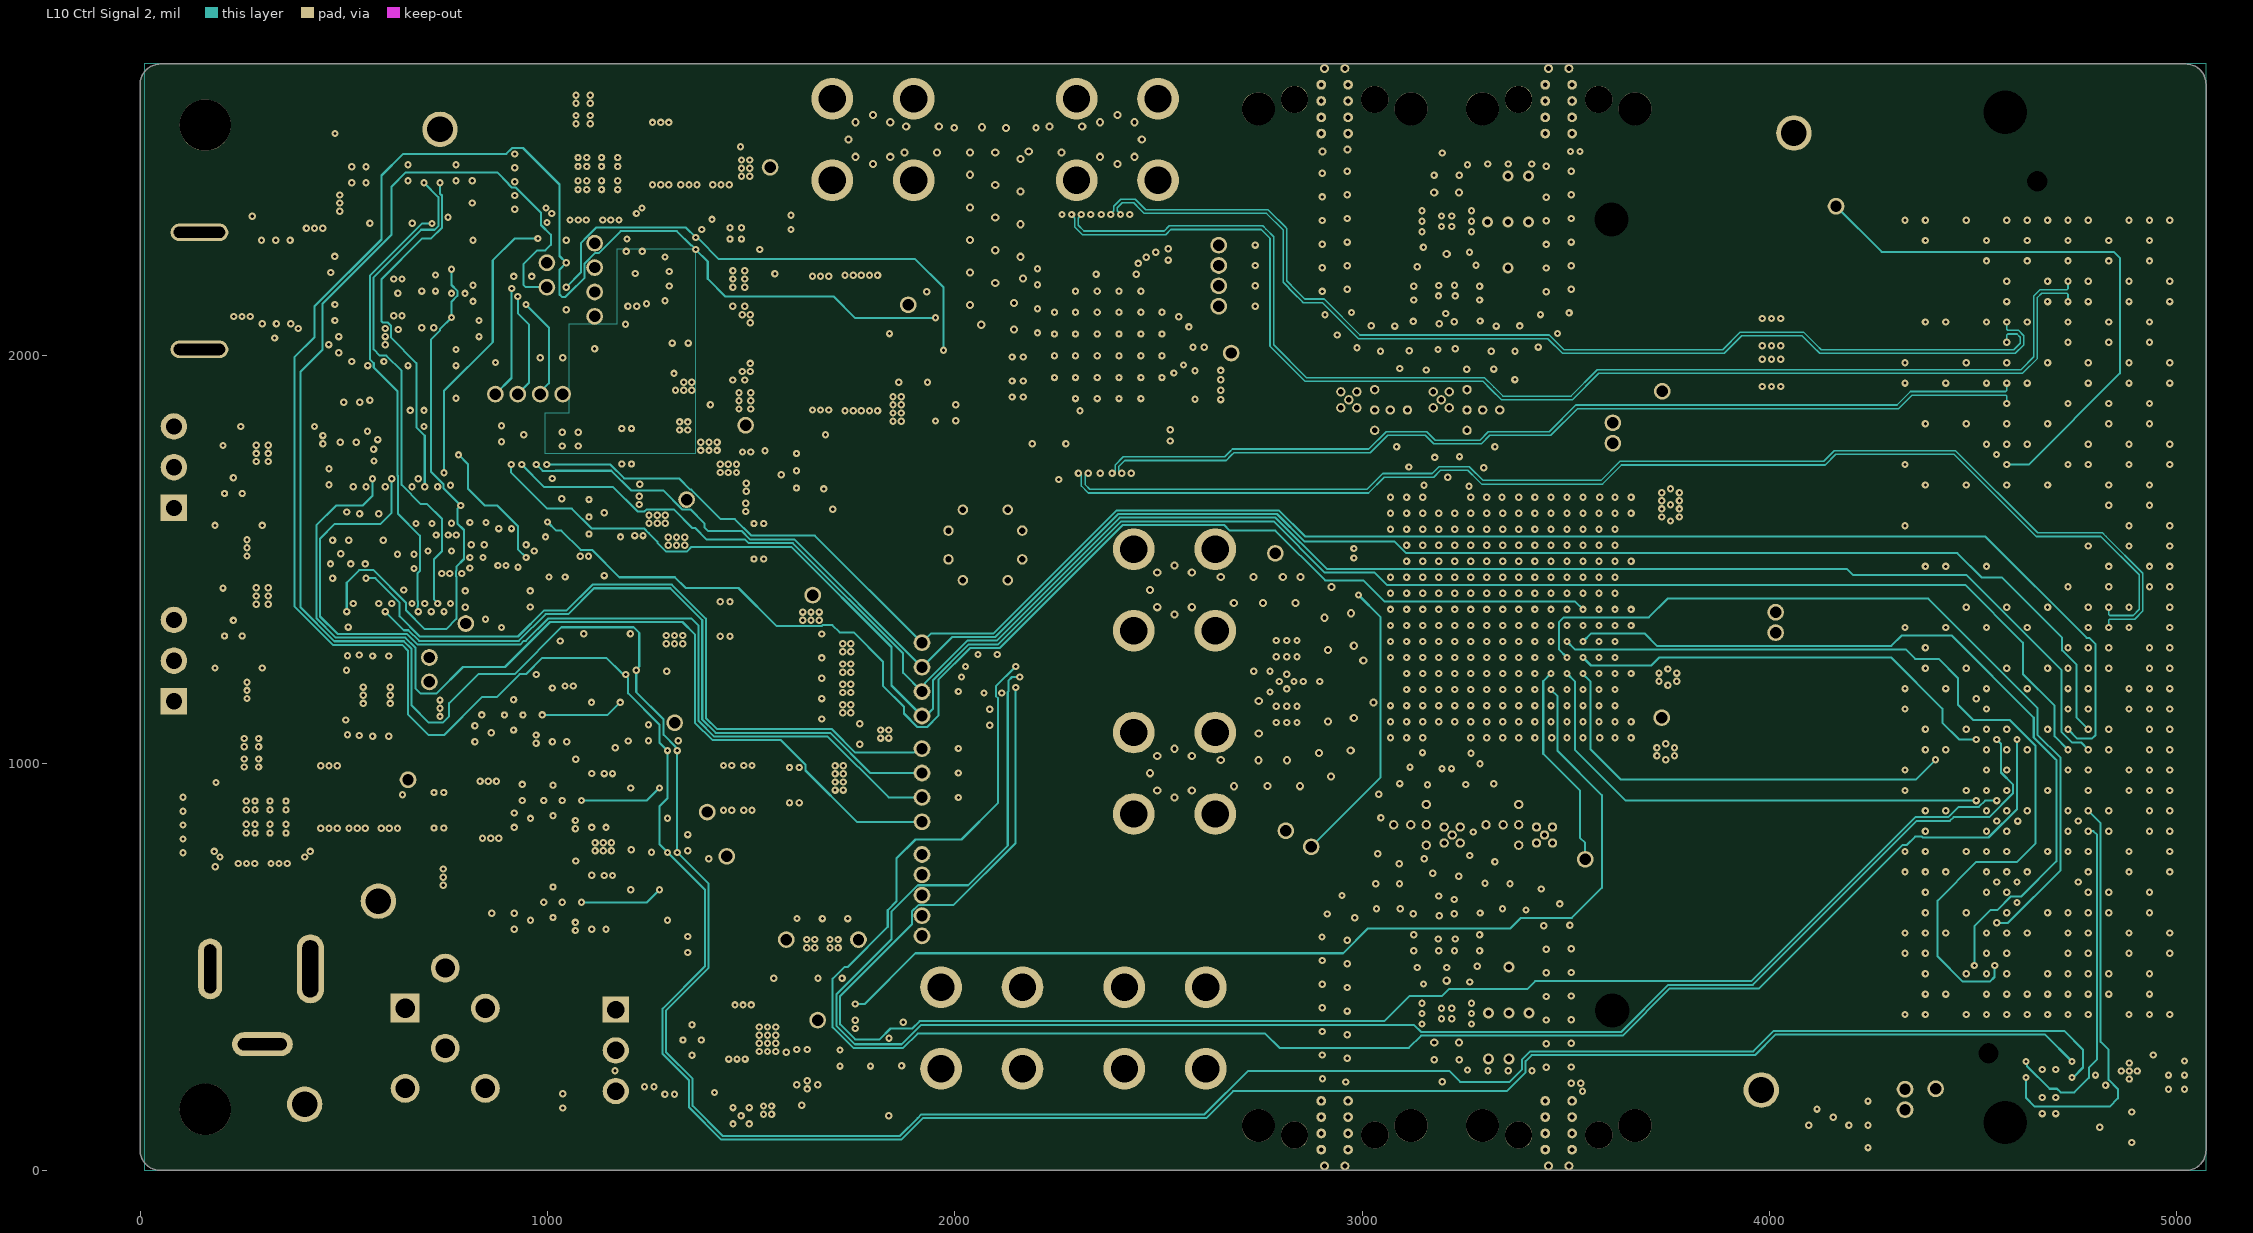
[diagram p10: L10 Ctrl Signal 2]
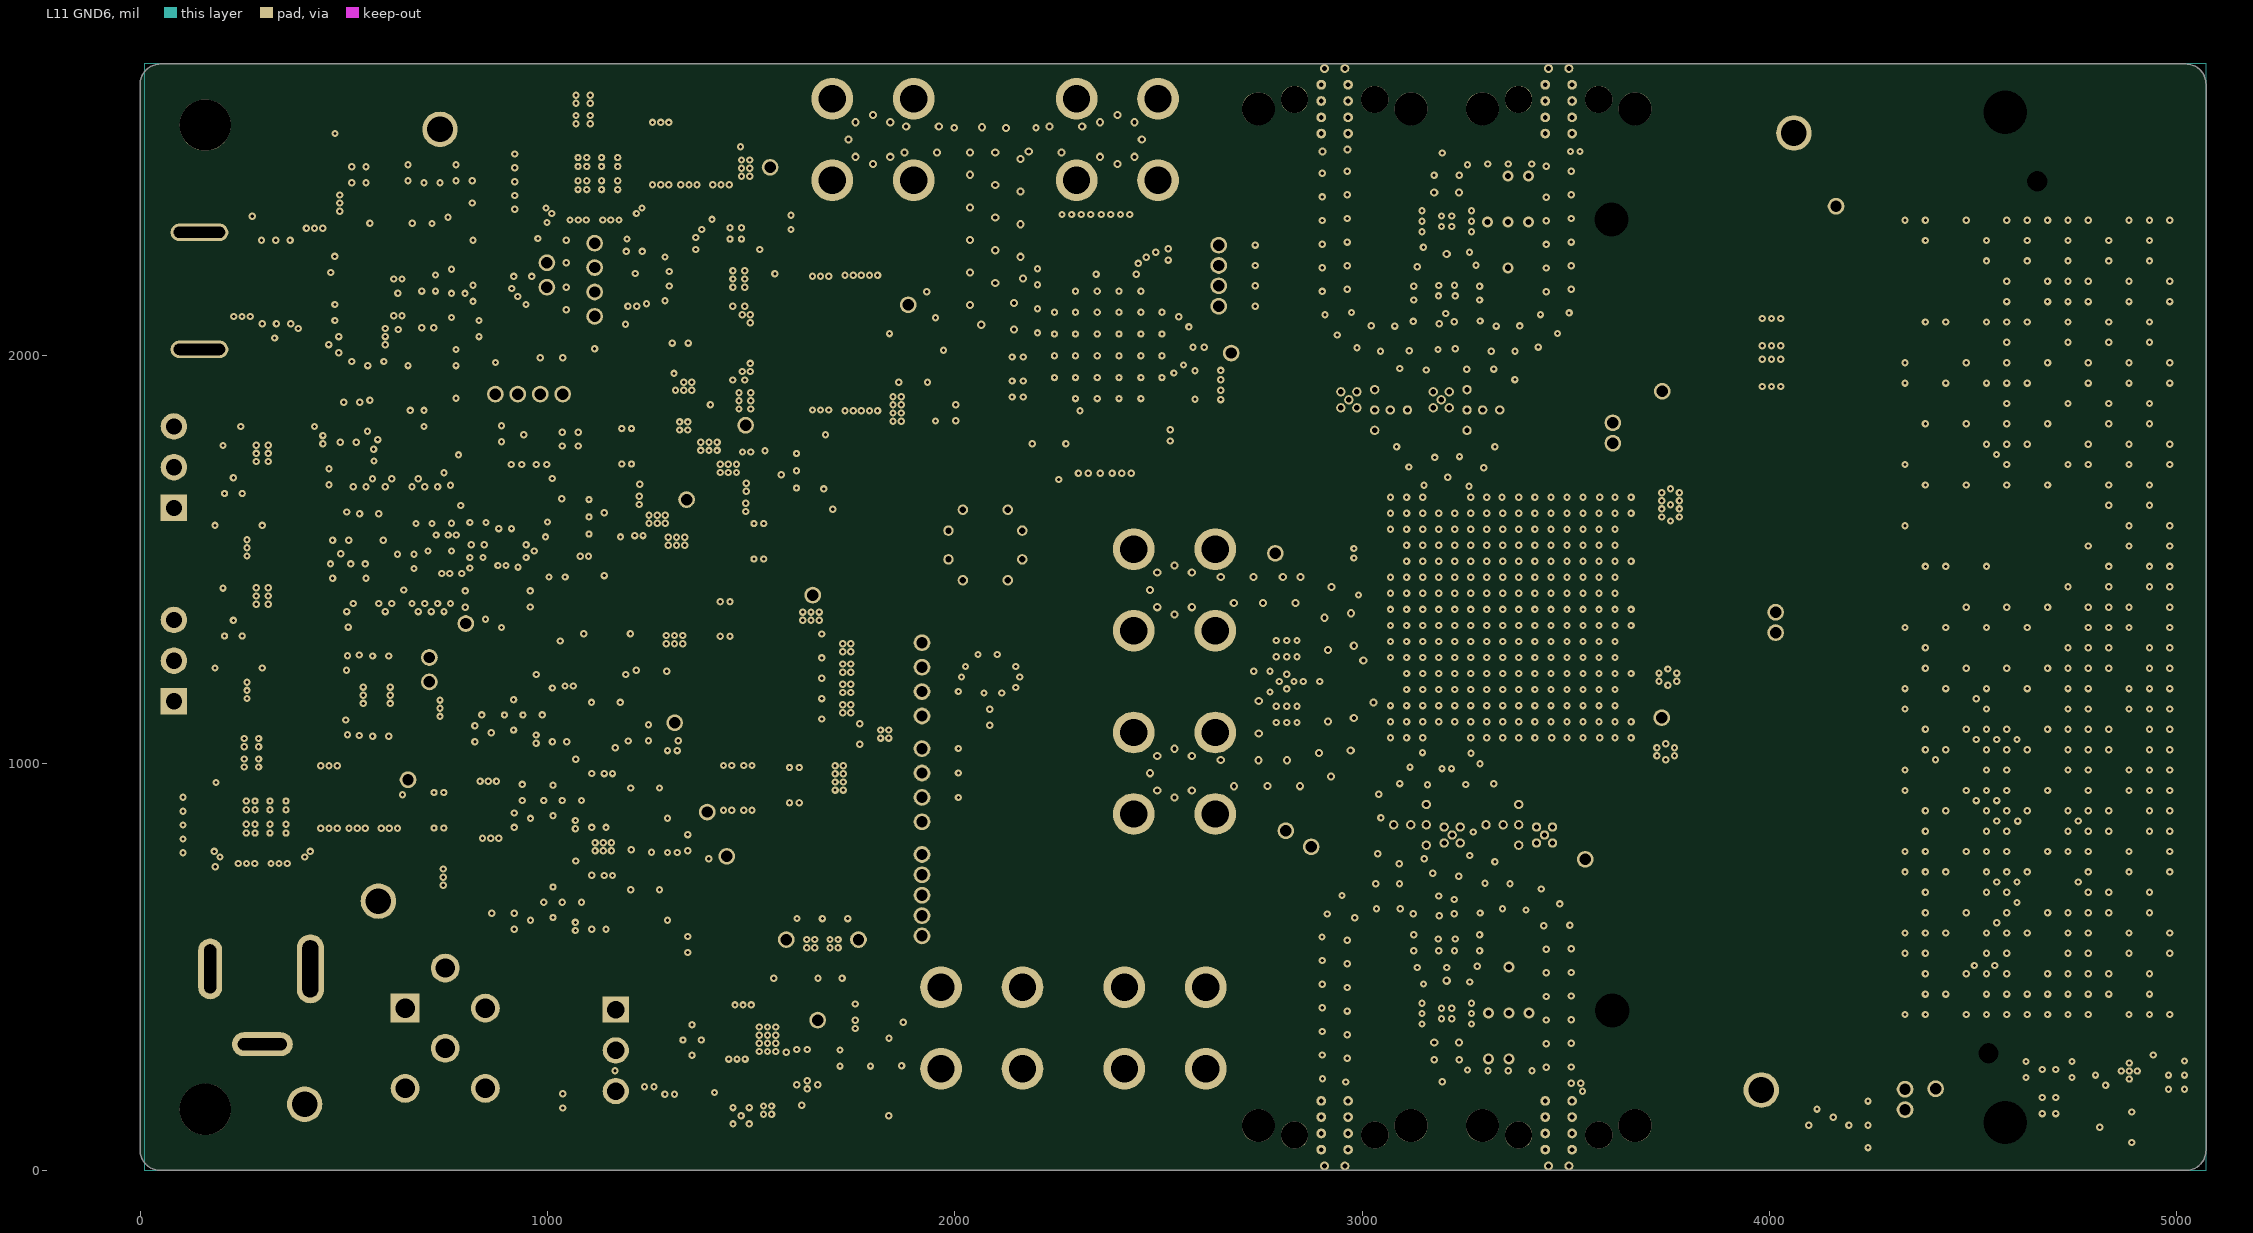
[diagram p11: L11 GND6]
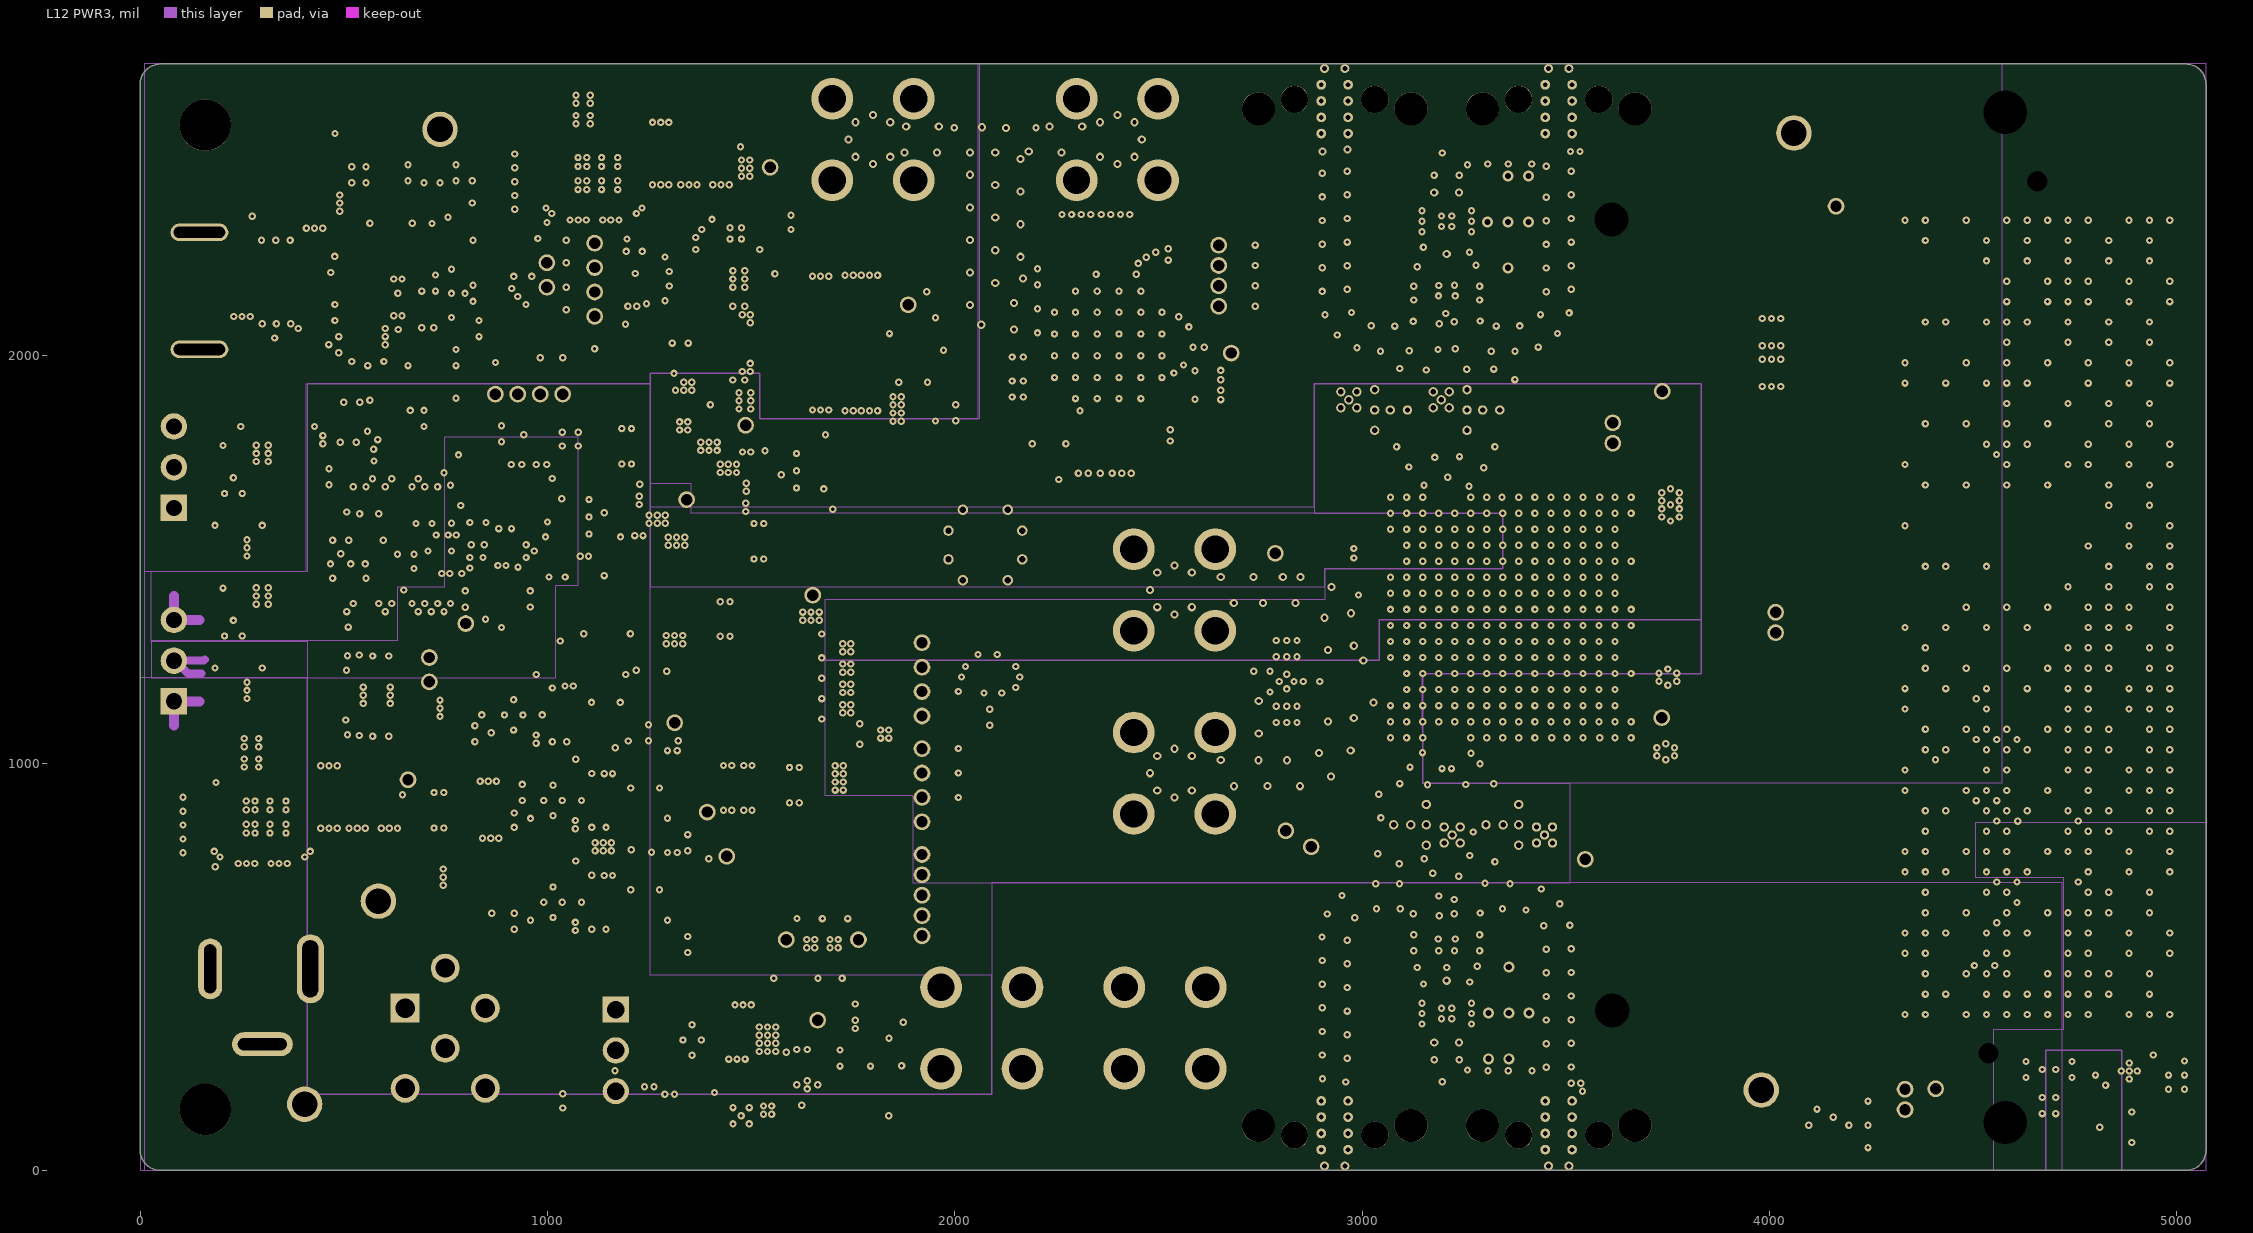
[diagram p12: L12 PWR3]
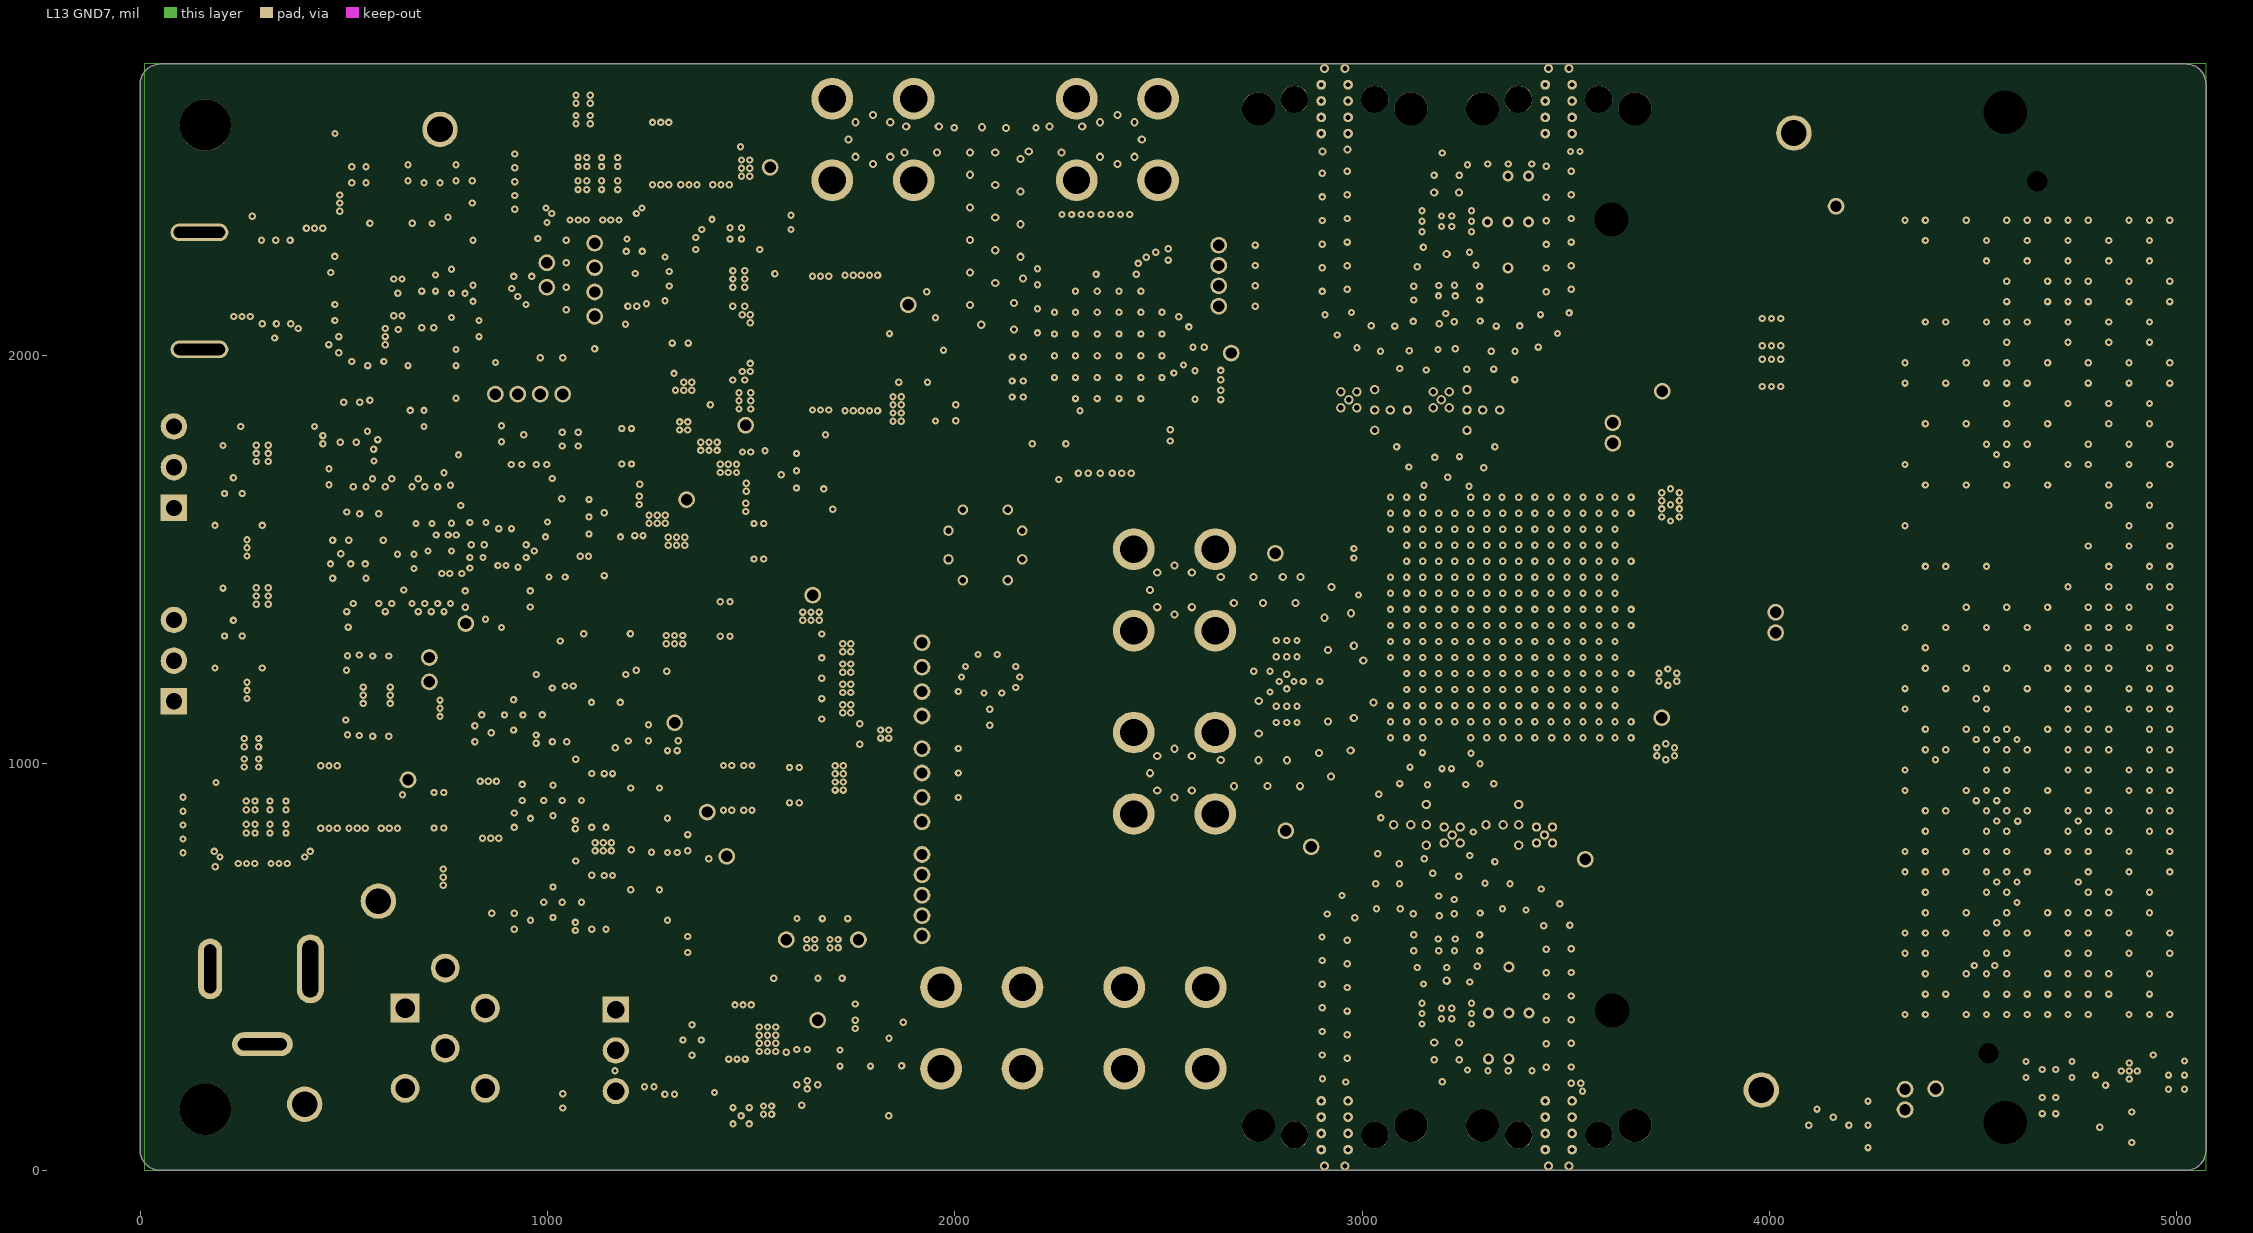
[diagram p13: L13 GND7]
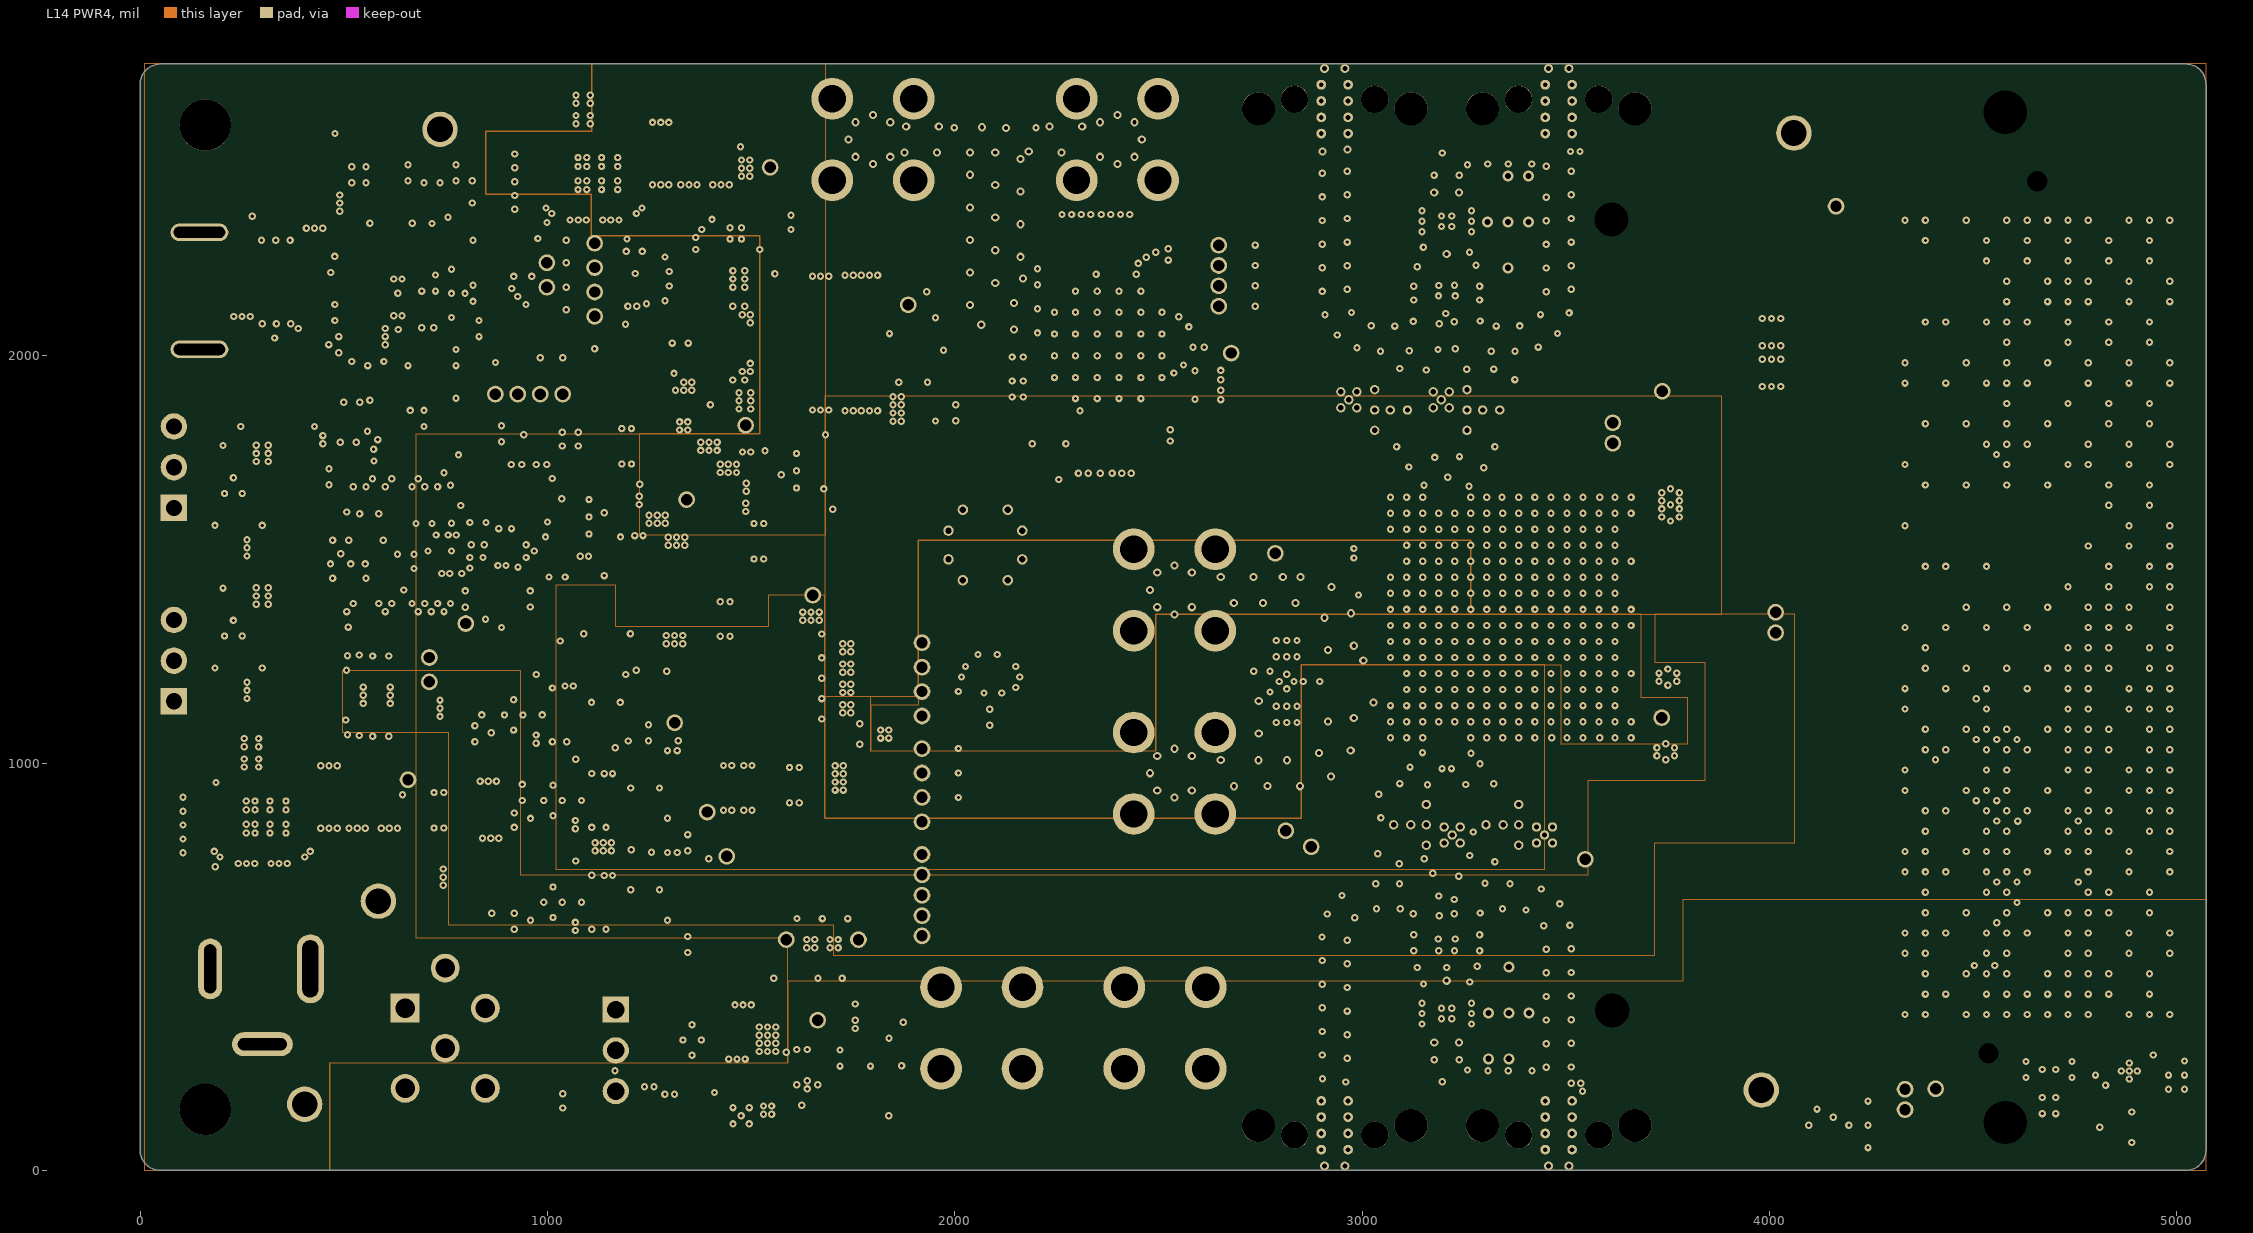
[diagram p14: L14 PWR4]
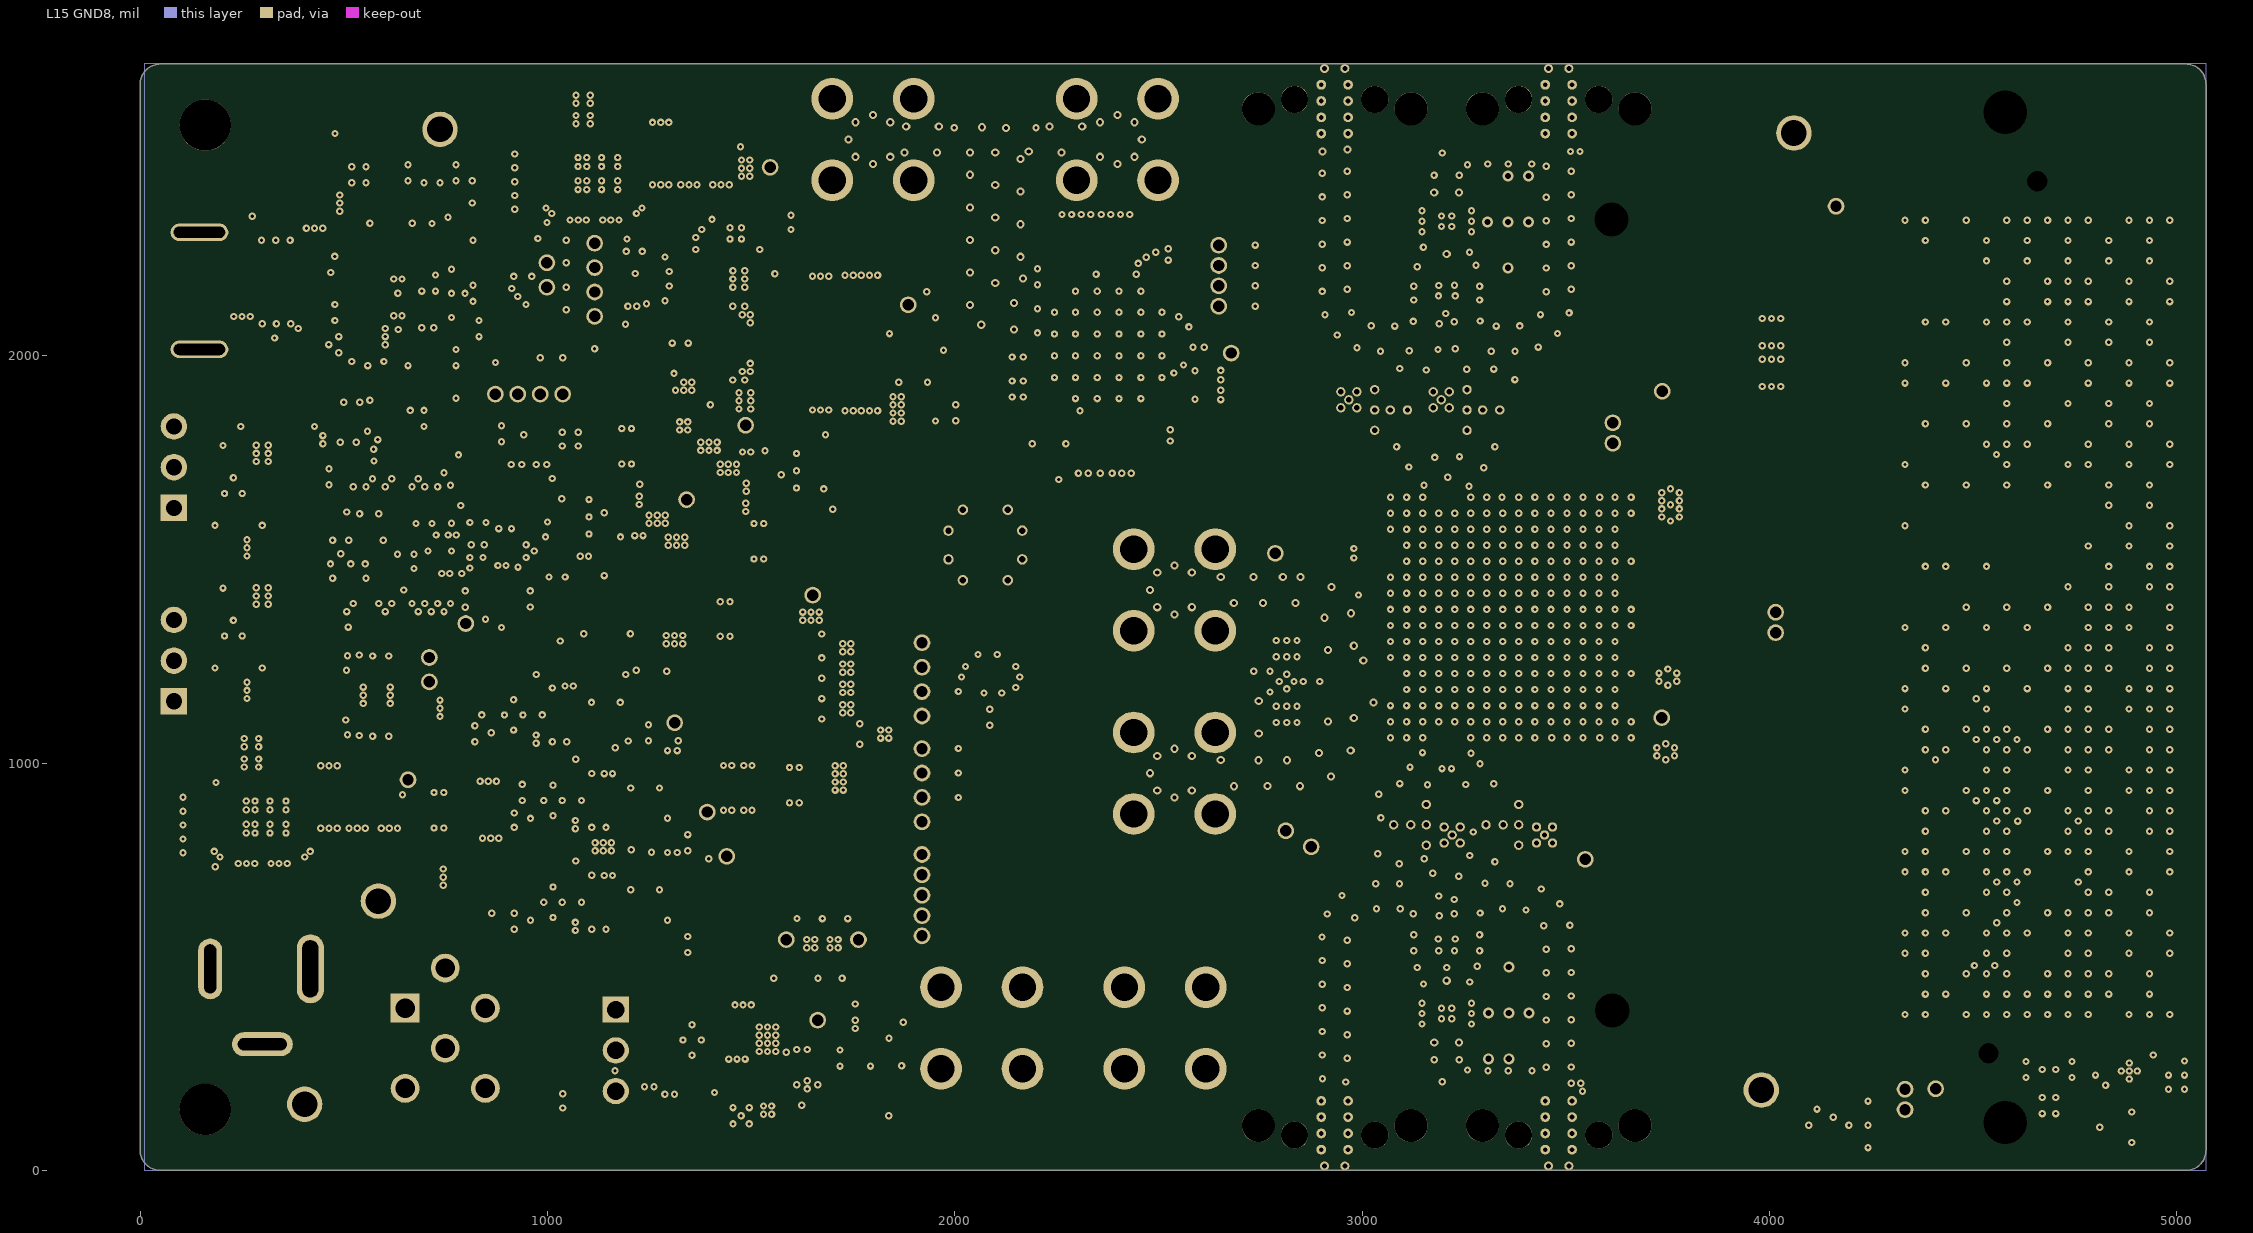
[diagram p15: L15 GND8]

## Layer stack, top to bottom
Top Solder: solder mask 0.4, Solder Resist, Dk 3.5
Top Layer: signal copper 1.4
Dielectric 1: core 6, Itera-mt40, Dk 3.33
L2 GND1: signal copper 1.4
Dielectric 2: prepreg 3, FR4-370HR, Dk 3.72
L3 PWR1: signal copper 1.4
Dielectric 3: prepreg 3, FR4-370HR, Dk 3.72
L4 GND2: signal copper 1.4
Dielectric 4: core 3, FR4-370HR, Dk 3.86
L5 PWR2: signal copper 1.4
Dielectric 5: prepreg 3, FR4-370HR, Dk 3.72
L6 GND3: signal copper 1.4
Dielectric 6: core 3, FR4-370HR, Dk 3.86
L7 Ctrl Signal 1: signal copper 1.4
Dielectric 8: prepreg 3, FR4-370HR, Dk 3.72
Dielectric 7: prepreg 3, FR4-370HR, Dk 3.72
L8 GND4: signal copper 1.4
Dielectric 9: core 6, FR4-370HR, Dk 3.86
L9 GND5: signal copper 1.4
Dielectric 11: prepreg 3, FR4-370HR, Dk 3.72
Dielectric 10: prepreg 3, FR4-370HR, Dk 3.72
L10 Ctrl Signal 2: signal copper 1.4
Dielectric 12: core 3, FR4-370HR, Dk 3.86
L11 GND6: signal copper 1.4
Dielectric 13: prepreg 3, FR4-370HR, Dk 3.72
L12 PWR3: signal copper 1.4
Dielectric 14: core 3, FR4-370HR, Dk 3.86
L13 GND7: signal copper 1.4
Dielectric 15: prepreg 3, FR4-370HR, Dk 3.72
L14 PWR4: signal copper 1.4
Dielectric 16: prepreg 3, FR4-370HR, Dk 3.72
L15 GND8: signal copper 1.4
Dielectric 17: core 6, Itera-mt40, Dk 3.33
Bottom Layer: signal copper 1.4
Bottom Solder: solder mask 0.4, Solder Resist, Dk 3.5

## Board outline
0,50 0,2666.54 cw(c50,2666.54) 50,2716.54 5021.81,2716.54 cw(c5021.81,2666.54) 5071.81,2666.54 5071.81,50 cw(c5021.81,50) 5021.81,0 50,0 cw(c50,50)

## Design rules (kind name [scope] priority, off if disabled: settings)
AcuteAngle [All] p0: scope1count=1 scope1_0_kind=Board scope1_0_value=Board scope2count=1 scope2_0_kind=Board scope2_0_value=Board commentlength=0 minimum=4.50000000000000E+0001
AcuteAngle [All] p1: minimum=4.50000000000000E+0001 checktracksonly=TRUE
AssemblyTestPointUsage [All] p0: scope1count=1 scope1_0_kind=Board scope1_0_value=Board scope2count=1 scope2_0_kind=Board scope2_0_value=Board commentlength=0
AssemblyTestPointUsage [All] p1: valid=2
AssemblyTestpoint [All] p0: scope1count=1 scope1_0_kind=Board scope1_0_value=Board scope2count=1 scope2_0_kind=Board scope2_0_value=Board commentlength=0
BackDrilling [All] p0: scope1count=1 scope1_0_kind=Net scope1_0_value=GND scope2count=1 scope2_0_kind=Board scope2_0_value=Board commentlength=0
BackDrilling [InNet('GND')] p1: maxstublength=10 usetopbackdrill=TRUE usebottombackdrill=TRUE holeoversize=1 holetolplus=0 holetolminus=0
BoardOutlineClearance BoardOutlineClearance_Poly_PWR [All] p0 off: scope1count=1 scope1_0_kind=Board scope1_0_value=Board scope2count=1 scope2_0_kind=Board scope2_0_value=Board commentlength=79 gap=25 // Protel DXP Scope 1 Expression Was: OnCopper and IsPoly and NOT InNet('GND')
BoardOutlineClearance BoardOutlineClearance_EDGE_Connectors [All] p0: scope1count=1 scope1_0_kind=Footprint scope1_0_value=1092-04A-14 scope2count=1 scope2_0_kind=Board scope2_0_value=Board commentlength=0 gap=25
BoardOutlineClearance BoardOutlineClearance_Poly_GND_Layer2 [All] p0 off: scope1count=1 scope1_0_kind=Board scope1_0_value=Board scope2count=1 scope2_0_kind=Board scope2_0_value=Board commentlength=98 gap=25 // Protel DXP Scope 1 Expression Was: OnCopper and IsPoly and InNet('GND') and OnLayer('L2 GND1')
BoardOutlineClearance BoardOutlineClearance_Poly_GND [All] p0 off: scope1count=1 scope1_0_kind=Board scope1_0_value=Board scope2count=1 scope2_0_kind=Board scope2_0_value=Board commentlength=75 gap=25 // Protel DXP Scope 1 Expression Was: OnCopper and IsPoly and InNet('GND')
BoardOutlineClearance BoardOutlineClearance_MountingHoles_1 [All] p0 off: scope1count=1 scope1_0_kind=Board scope1_0_value=Board scope2count=1 scope2_0_kind=Board scope2_0_value=Board commentlength=86 gap=39.37 // Protel DXP Scope 1 Expression Was: OnCopper and InComponentClass('Mounting Holes')
BoardOutlineClearance [All] p0 off: scope1count=1 scope1_0_kind=Board scope1_0_value=Board scope2count=1 scope2_0_kind=Board scope2_0_value=Board commentlength=258 gap=25 // Protel DXP Scope 1 Expression Was: OnCopper and Not InComponentClass('Logo') and not InComponentClass('FiducialMark') and not InRegion(1000,500,4000,800) and not InPoly and not HasFootprint('HiRose-HK-LR-SR2-SWM1092-04A-MicroStirp-6mil-Female-Backdrill')
BoardOutlineClearance BoardOutlineClearance_Poly [All] p0 off: scope1count=1 scope1_0_kind=Board scope1_0_value=Board scope2count=1 scope2_0_kind=Board scope2_0_value=Board commentlength=58 gap=25 // Protel DXP Scope 1 Expression Was: OnCopper and IsPoly
BoardOutlineClearance BoardOutlineClearance_EDGE_Connectors [HasFootprint('1092-04A-14')] p1: gap=25 ignorepadtopadclearanceinfootprint=FALSE except(0: Arc-OutlineEdge Track-OutlineEdge SMDPad-OutlineEdge THPad-OutlineEdge Via-OutlineEdge Fill-OutlineEdge Poly-OutlineEdge Region-OutlineEdge Text-OutlineEdge)
BoardOutlineClearance BoardOutlineClearance_Poly_GND_Layer2 [OnCopper and IsPoly and InNet('GND') and OnLayer('L2 GND1')] p2 off: gap=25 ignorepadtopadclearanceinfootprint=FALSE except(0: Poly-OutlineEdge)
BoardOutlineClearance BoardOutlineClearance_Poly_GND [OnCopper and IsPoly and InNet('GND')] p3: gap=25 ignorepadtopadclearanceinfootprint=FALSE except(15: Poly-OutlineEdge)
BoardOutlineClearance BoardOutlineClearance_Poly_PWR [OnCopper and IsPoly and NOT InNet('GND')] p4: gap=25 ignorepadtopadclearanceinfootprint=FALSE
BoardOutlineClearance BoardOutlineClearance_MountingHoles_1 [OnCopper and InComponentClass('Mounting Holes')] p5: gap=39.37 ignorepadtopadclearanceinfootprint=FALSE
BoardOutlineClearance BoardOutlineClearance_Poly [OnCopper and IsPoly] p6: gap=25 ignorepadtopadclearanceinfootprint=FALSE
BoardOutlineClearance [OnCopper and Not InComponentClass('Logo') and not InComponentClass('FiducialMark') and not InRegion(1000,500,4000,800) and not InPoly and not HasFootprint('HiRose-HK-LR-SR2-SWM1092-04A-MicroStirp-6mil-Female-Backdrill')] p7: gap=25 ignorepadtopadclearanceinfootprint=FALSE
Clearance Clearance_BGA [All] p0 off: scope1count=1 scope1_0_kind=Board scope1_0_value=Board scope2count=1 scope2_0_kind=Board scope2_0_value=Board commentlength=83 gap=5 // Protel DXP Scope 2 Expression Was: WithinRoom('DAC39RF10') or WithinRoom('FMC')
Clearance Clearance_Poly_GND [All] p0 off: scope1count=1 scope1_0_kind=Board scope1_0_value=Board scope2count=1 scope2_0_kind=Board scope2_0_value=Board commentlength=65 gap=5 // Protel DXP Scope 1 Expression Was: InPolygon and InNet('GND')
Clearance [All] p0 off: scope1count=1 scope1_0_kind=Board scope1_0_value=Board scope2count=1 scope2_0_kind=Board scope2_0_value=Board commentlength=64 gap=5 // Protel DXP Scope 2 Expression Was: not InAnyDifferentialPair
Clearance Clearance_FiducialMark [All] p0 off: scope1count=1 scope1_0_kind=Board scope1_0_value=Board scope2count=1 scope2_0_kind=Board scope2_0_value=Board commentlength=81 gap=0 // Protel DXP Scope 2 Expression Was: IsPad and InComponentClass('FiducialMark')
Clearance Clearance_Poly [All] p0 off: scope1count=1 scope1_0_kind=Board scope1_0_value=Board scope2count=1 scope2_0_kind=Board scope2_0_value=Board commentlength=48 gap=5 // Protel DXP Scope 1 Expression Was: InPolygon
Clearance Clearance_Keepouts [All] p0 off: scope1count=1 scope1_0_kind=Board scope1_0_value=Board scope2count=1 scope2_0_kind=Board scope2_0_value=Board commentlength=99 gap=0 // Protel DXP Scope 2 Expression Was: ((IsTrack Or IsArc) And Not InPoly) And IsFree and IsKeepOut
Clearance Clearance_BGA [not InAnyDifferentialPair vs WithinRoom('DAC39RF10') or WithinRoom('FMC')] p1: gap=5 ignorepadtopadclearanceinfootprint=TRUE except(4: Arc-Arc Arc-Track Arc-SMDPad Arc-THPad Arc-Fill Arc-Poly Arc-Region Arc-Text Track-Track Track-SMDPad Track-THPad Track-Fill Track-Poly Track-Region Track-Text; 8: Arc-Hole Track-Hole; 8.1: Arc-Via Track-Via; 10: SMDPad-SMDPad THPad-Fill THPad-Poly THPad-Region)
Clearance Clearance_Poly_GND [InPolygon and InNet('GND')] p2: gap=5 ignorepadtopadclearanceinfootprint=TRUE except(8: Arc-Hole Track-Hole SMDPad-Hole THPad-Hole Via-Hole Fill-Hole Poly-Hole Region-Hole Text-Hole; 10: SMDPad-Fill SMDPad-Poly SMDPad-Region THPad-Fill THPad-Poly THPad-Region; 15: Arc-Fill Arc-Poly Arc-Region Track-Fill Track-Poly Track-Region Fill-Fill Fill-Poly Fill-Region Poly-Poly Poly-Region Region-Region)
Clearance Clearance_Keepouts [((IsTrack Or IsArc) And Not InPoly) And IsFree and IsKeepOut vs ((IsTrack Or IsArc) And Not InPoly) And IsFree and IsKeepOut] p3: gap=0 ignorepadtopadclearanceinfootprint=FALSE
Clearance Clearance_Poly [InPolygon] p4: gap=5 ignorepadtopadclearanceinfootprint=TRUE except(8: Arc-Hole Track-Hole SMDPad-Hole THPad-Hole Via-Hole Fill-Hole Poly-Hole Region-Hole Text-Hole; 15: Fill-Fill Fill-Poly Fill-Region Poly-Poly Poly-Region Region-Region)
Clearance Clearance_FiducialMark [IsKeepOut and InComponentClass('FiducialMark') vs IsPad and InComponentClass('FiducialMark')] p5: gap=0 ignorepadtopadclearanceinfootprint=FALSE
Clearance [All vs not InAnyDifferentialPair] p6: gap=5 ignorepadtopadclearanceinfootprint=TRUE except(4: Arc-Arc Arc-Track Arc-SMDPad Arc-THPad Arc-Via Arc-Fill Arc-Poly Arc-Region Arc-Text Track-Track Track-SMDPad Track-THPad Track-Via Track-Fill Track-Poly Track-Region Track-Text; 8: Arc-Hole Track-Hole SMDPad-Hole THPad-Hole Via-Hole Fill-Hole Poly-Hole Region-Hole Text-Hole; 10: SMDPad-SMDPad THPad-Fill THPad-Poly THPad-Region)
ComponentClearance ComponentClearance_THtoSMT_NetTieVias [All] p0 off: scope1count=1 scope1_0_kind=Footprint scope1_0_value=Net-Tie-Via-8mil scope2count=1 scope2_0_kind=Board scope2_0_value=Board commentlength=53 gap=0 collisioncheckmode=3 // Protel DXP Scope 2 Expression Was: IsSMTComponent
ComponentClearance ComponentClearance_ProbePoints_TH [All] p0: scope1count=1 scope1_0_kind=Footprint scope1_0_value=ProbePoint_TH_40mil scope2count=1 scope2_0_kind=Board scope2_0_value=Board commentlength=0 gap=10 collisioncheckmode=3
ComponentClearance "ComponentClearance Part Overlap" [All] p0 off: scope1count=1 scope1_0_kind=Board scope1_0_value=Board scope2count=1 scope2_0_kind=Board scope2_0_value=Board commentlength=83 gap=0 collisioncheckmode=3 // Protel DXP Scope 1 Expression Was: (InComponent('C105') OR InComponent('C112'))
ComponentClearance [All] p0: scope1count=1 scope1_0_kind=Board scope1_0_value=Board scope2count=1 scope2_0_kind=Board scope2_0_value=Board commentlength=0 gap=10 collisioncheckmode=3
ComponentClearance ComponentClearance_THtoTH [All] p0 off: scope1count=1 scope1_0_kind=Board scope1_0_value=Board scope2count=1 scope2_0_kind=Board scope2_0_value=Board commentlength=54 gap=0 collisioncheckmode=3 // Protel DXP Scope 2 Expression Was: IsThruComponent
ComponentClearance ComponentClearance_THtoSMT [All] p0 off: scope1count=1 scope1_0_kind=Board scope1_0_value=Board scope2count=1 scope2_0_kind=Board scope2_0_value=Board commentlength=53 gap=0 collisioncheckmode=3 // Protel DXP Scope 2 Expression Was: IsSMTComponent
ComponentClearance ComponentClearance_SmallPassives [All] p0 off: scope1count=1 scope1_0_kind=Board scope1_0_value=Board scope2count=1 scope2_0_kind=Board scope2_0_value=Board commentlength=508 gap=10 collisioncheckmode=3 // Protel DXP Scope 2 Expression Was: HasFootprint('0201*') or HasFootprint('0402*') or HasFootprint('0508') or HasFootprint('0603*') or HasFootprint('0612') or HasFootprint('0805*') or HasFootprint('0815*') or HasFootprint('0830*') or HasFootprint('1206*') or HasFootprint('1210*') or HasFootprint('1808*') or HasFootprint('1812*') or HasFootprint('1825*') or HasFootprint('2010*') or HasFootprint('2220*') or HasFootprint('2225*') or HasFootprint('2512*') or HasFootprint('2728*') or HasFootprint('3518*')
ComponentClearance ComponentClearance_MountingHoles [All] p0: scope1count=1 scope1_0_kind=ComponentClass scope1_0_value="Mounting Holes" scope2count=1 scope2_0_kind=Board scope2_0_value=Board commentlength=0 gap=200 collisioncheckmode=3
ComponentClearance ComponentClearance_ScrewToNut [All] p0 off: scope1count=1 scope1_0_kind=Board scope1_0_value=Board scope2count=1 scope2_0_kind=Board scope2_0_value=Board commentlength=71 gap=5 collisioncheckmode=3 // Protel DXP Scope 2 Expression Was: (HasFootprint('Keystone_1902C'))
ComponentClearance ComponentClearance_Logo [All] p0: scope1count=1 scope1_0_kind=ComponentClass scope1_0_value=Logo scope2count=1 scope2_0_kind=Board scope2_0_value=Board commentlength=0 gap=50 collisioncheckmode=3
ComponentClearance ComponentClearance_Shunt [All] p0: scope1count=1 scope1_0_kind=ComponentClass scope1_0_value=Header scope2count=1 scope2_0_kind=ComponentClass scope2_0_value=Shunt commentlength=0 gap=0 collisioncheckmode=3
ComponentClearance ComponentClearance_MountingHoles_FiducialMarks [All] p0: scope1count=1 scope1_0_kind=ComponentClass scope1_0_value="Mounting Holes" scope2count=1 scope2_0_kind=ComponentClass scope2_0_value=FiducialMark commentlength=0 gap=50 collisioncheckmode=3
ComponentClearance "ComponentClearance Part Overlap" [(InComponent('C105') OR InComponent('C112'))] p1: gap=0 collisioncheckmode=3 verticalgap=0 showdistances=FALSE
ComponentClearance ComponentClearance_ProbePoints_TH [HasFootprint('ProbePoint_TH_40mil')] p2: gap=10 collisioncheckmode=3 verticalgap=0 showdistances=FALSE donotcheckwithout3dbody=TRUE
ComponentClearance ComponentClearance_THtoSMT_NetTieVias [HasFootprint('Net-Tie-Via-8mil') vs IsSMTComponent] p3: gap=0 collisioncheckmode=3 verticalgap=0 showdistances=FALSE donotcheckwithout3dbody=TRUE
ComponentClearance ComponentClearance_MountingHoles_FiducialMarks [InComponentClass('Mounting Holes') vs InComponentClass('FiducialMark')] p4: gap=50 collisioncheckmode=3 verticalgap=10 showdistances=FALSE
ComponentClearance ComponentClearance_Shunt [InComponentClass('Header') vs InComponentClass('Shunt')] p5: gap=0 collisioncheckmode=3 verticalgap=0 showdistances=FALSE
ComponentClearance ComponentClearance_Logo [InComponentClass('Logo')] p6: gap=50 collisioncheckmode=3 verticalgap=10 showdistances=FALSE
ComponentClearance ComponentClearance_ScrewToNut [(HasFootprint('NY PMS 440 0025 PH')) vs (HasFootprint('Keystone_1902C'))] p7: gap=5 collisioncheckmode=3 verticalgap=10 showdistances=FALSE
ComponentClearance ComponentClearance_MountingHoles [InComponentClass('Mounting Holes')] p8: gap=200 collisioncheckmode=3 verticalgap=100000 showdistances=FALSE
ComponentClearance ComponentClearance_SmallPassives [HasFootprint('0201*') or HasFootprint('0402*') or HasFootprint('0508') or HasFootprint('0603*') or HasFootprint('0612') or HasFootprint('0805*') or HasFootprint('0815*') or HasFootprint('0830*') or HasFootprint('1206*') or HasFootprint('1210*') or HasFootprint('1808*') or HasFootprint('1812*') or HasFootprint('1825*') or HasFootprint('2010*') or HasFootprint('2220*') or HasFootprint('2225*') or HasFootprint('2512*') or HasFootprint('2728*') or HasFootprint('3518*') vs HasFootprint('0201*') or HasFootprint('0402*') or HasFootprint('0508') or HasFootprint('0603*') or HasFootprint('0612') or HasFootprint('0805*') or HasFootprint('0815*') or HasFootprint('0830*') or HasFootprint('1206*') or HasFootprint('1210*') or HasFootprint('1808*') or HasFootprint('1812*') or HasFootprint('1825*') or HasFootprint('2010*') or HasFootprint('2220*') or HasFootprint('2225*') or HasFootprint('2512*') or HasFootprint('2728*') or HasFootprint('3518*')] p9: gap=10 collisioncheckmode=3 verticalgap=10 showdistances=FALSE
ComponentClearance ComponentClearance_THtoSMT [IsThruComponent vs IsSMTComponent] p10: gap=0 collisioncheckmode=3 verticalgap=0 showdistances=FALSE
ComponentClearance ComponentClearance_THtoTH [IsThruComponent vs IsThruComponent] p11: gap=0 collisioncheckmode=3 verticalgap=0 showdistances=FALSE
ComponentClearance [All] p12: gap=10 collisioncheckmode=3 verticalgap=10 showdistances=FALSE
DiffPairsRouting [All] p0: scope1count=1 scope1_0_kind=Board scope1_0_value=Board scope2count=1 scope2_0_kind=Board scope2_0_value=Board commentlength=0
DiffPairsRouting [All] p1: maxlimit=15 minlimit=3 mostfreqgap=4 toplayer_minwidth=3 toplayer_maxwidth=15 toplayer_prefwidth=6.3 midlayer1_minwidth=3 midlayer1_maxwidth=15 midlayer1_prefwidth=5 midlayer2_minwidth=3 midlayer2_maxwidth=15 midlayer2_prefwidth=5 midlayer3_minwidth=3 midlayer3_maxwidth=15 midlayer3_prefwidth=5 midlayer4_minwidth=3 midlayer4_maxwidth=15 midlayer4_prefwidth=5 midlayer5_minwidth=3 midlayer5_maxwidth=15 midlayer5_prefwidth=5 midlayer6_minwidth=3 midlayer6_maxwidth=15 midlayer6_prefwidth=5 midlayer7_minwidth=3 midlayer7_maxwidth=15 midlayer7_prefwidth=5 midlayer8_minwidth=3 midlayer8_maxwidth=15 midlayer8_prefwidth=5 midlayer9_minwidth=3 midlayer9_maxwidth=15 midlayer9_prefwidth=5 midlayer10_minwidth=3 midlayer10_maxwidth=15 midlayer10_prefwidth=5 midlayer11_prefgap=5 midlayer11_minwidth=3 midlayer11_maxwidth=15 midlayer11_prefwidth=4 midlayer12_prefgap=5 midlayer12_minwidth=3 midlayer12_maxwidth=15 midlayer12_prefwidth=4 midlayer13_minwidth=3 midlayer13_maxwidth=15 midlayer13_prefwidth=5 midlayer14_minwidth=3 midlayer14_maxwidth=15 midlayer14_prefwidth=5 bottomlayer_prefgap=3.5 bottomlayer_minwidth=3 bottomlayer_maxwidth=15 bottomlayer_prefwidth=6.25 maxuncoupledlength=1000
FabricationTestPointUsage TestPointUsage [All] p0: scope1count=1 scope1_0_kind=Board scope1_0_value=Board scope2count=1 scope2_0_kind=Board scope2_0_value=Board commentlength=0 valid=2 allowmultiple=FALSE
FabricationTestPointUsage TestPointUsage [All] p1: valid=2 allowmultiple=FALSE
FabricationTestpoint Testpoint [All] p0: scope1count=1 scope1_0_kind=Board scope1_0_value=Board scope2count=1 scope2_0_kind=Board scope2_0_value=Board commentlength=0 side=3 testpointundercomponent=TRUE minsize=40 maxsize=100 preferedsize=60 minholesize=0 maxholesize=40 preferedholesize=32 testpointgrid=1
FabricationTestpoint Testpoint [All] p1: side=3 testpointundercomponent=TRUE minsize=40 maxsize=100 preferedsize=60 minholesize=0 maxholesize=40 preferedholesize=32 testpointgrid=1 allowsidetop=TRUE allowsidebottom=TRUE usegrid=TRUE gridtolerance=0.01
FanoutControl Fanout_Small [All] p0 off: scope1count=1 scope1_0_kind=Board scope1_0_value=Board scope2count=1 scope2_0_kind=Board scope2_0_value=Board commentlength=84 // Protel DXP Scope 1 Expression Was: (CompPinCount < 5)   Fanout_Small (Default Rule)
FanoutControl Fanout_Default [All] p0: scope1count=1 scope1_0_kind=Board scope1_0_value=Board scope2count=1 scope2_0_kind=Board scope2_0_value=Board commentlength=30 // Fanout_Default (Default Rule)
FanoutControl Fanout_SOIC [All] p0 off: scope1count=1 scope1_0_kind=Board scope1_0_value=Board scope2count=1 scope2_0_kind=Board scope2_0_value=Board commentlength=71 // Protel DXP Scope 1 Expression Was: IsSOIC   Fanout_SOIC (Default Rule)
FanoutControl Fanout_BGA [All] p0 off: scope1count=1 scope1_0_kind=Board scope1_0_value=Board scope2count=1 scope2_0_kind=Board scope2_0_value=Board commentlength=69 // Protel DXP Scope 1 Expression Was: IsBGA   Fanout_BGA (Default Rule)
FanoutControl Fanout_LCC [All] p0 off: scope1count=1 scope1_0_kind=Board scope1_0_value=Board scope2count=1 scope2_0_kind=Board scope2_0_value=Board commentlength=69 // Protel DXP Scope 1 Expression Was: IsLCC   Fanout_LCC (Default Rule)
FanoutControl Fanout_LCC [IsLCC] p1: bgadir=Out bgaviamode=Centered fanoutstyle=Auto fanoutdirection=Alternating viagrid=1 // Fanout_LCC (Default Rule)
FanoutControl Fanout_BGA [IsBGA] p2: bgadir=Out bgaviamode=Centered fanoutstyle=Auto fanoutdirection=Alternating viagrid=1 // Fanout_BGA (Default Rule)
FanoutControl Fanout_Default [All] p4: bgadir=Out bgaviamode=Centered fanoutstyle=Auto fanoutdirection=Alternating viagrid=1 // Fanout_Default (Default Rule)
FanoutControl Fanout_Small [(CompPinCount < 5)] p5: bgadir=Out bgaviamode=Centered fanoutstyle=Auto fanoutdirection=OutThenIn viagrid=1 // Fanout_Small (Default Rule)
Height [All] p0: scope1count=1 scope1_0_kind=Board scope1_0_value=Board scope2count=1 scope2_0_kind=Board scope2_0_value=Board commentlength=0
HoleSize [All] p0: scope1count=1 scope1_0_kind=Board scope1_0_value=Board scope2count=1 scope2_0_kind=Board scope2_0_value=Board commentlength=0 absolutevalues=TRUE maxlimit=251 minlimit=7.87 maxpercent=80.000 minpercent=20.000
HoleSize [All] p1: absolutevalues=TRUE maxlimit=251 minlimit=7.87 maxpercent=80.000 minpercent=20.000
HoleToHoleClearance [All] p0: scope1count=1 scope1_0_kind=Board scope1_0_value=Board scope2count=1 scope2_0_kind=Board scope2_0_value=Board commentlength=0
HoleToHoleClearance HoleToHoleClearance_MarkiBalun [All] p0 off: scope1count=1 scope1_0_kind=Board scope1_0_value=Board scope2count=1 scope2_0_kind=Board scope2_0_value=Board commentlength=79 // Protel DXP Scope 1 Expression Was: (InComponent('t4') OR InComponent('t5'))
HoleToHoleClearance HoleToHoleClearance_MarkiBalun [(InComponent('t4') OR InComponent('t5'))] p1: gap=7 allowstackedmicrovias=TRUE
HoleToHoleClearance [All] p2: gap=8 allowstackedmicrovias=TRUE
LayerPairs [All] p0: scope1count=1 scope1_0_kind=Board scope1_0_value=Board scope2count=1 scope2_0_kind=Board scope2_0_value=Board commentlength=0 enforce=TRUE
Length DAC_SYSREF [All] p0 off: scope1count=1 scope1_0_kind=Board scope1_0_value=Board scope2count=1 scope2_0_kind=Board scope2_0_value=Board commentlength=79 maxlimit=1135 minlimit=1133 // Protel DXP Scope 1 Expression Was: InNet('NetC296_2') or InNet('NetC298_2')
Length "Clk LMX to Switch" [All] p0 off: scope1count=1 scope1_0_kind=Board scope1_0_value=Board scope2count=1 scope2_0_kind=Board scope2_0_value=Board commentlength=71 maxlimit=912 minlimit=911 // Protel DXP Scope 1 Expression Was: InNet('CLK_n') or InNet('CLK_p')
Length DAC_SYSREF [InNet('NetC296_2') or InNet('NetC298_2')] p1: maxlimit=1135 minlimit=1133
Length "Clk LMX to Switch" [InNet('CLK_n') or InNet('CLK_p')] p2: maxlimit=912 minlimit=911
MinimumAnnularRing [All] p0: scope1count=1 scope1_0_kind=Board scope1_0_value=Board scope2count=1 scope2_0_kind=Board scope2_0_value=Board commentlength=0 minimumring=0
MinimumAnnularRing MinimumAnnularRing_ThermalPadVias [All] p0 off: scope1count=1 scope1_0_kind=Board scope1_0_value=Board scope2count=1 scope2_0_kind=Board scope2_0_value=Board commentlength=63 minimumring=0 // Protel DXP Scope 1 Expression Was: IsVia and InAnyComponent
MinimumAnnularRing MinimumAnnularRing_ThermalPadVias [IsVia and InAnyComponent] p1: minimumring=0
MinimumAnnularRing [All] p2: minimumring=0
MinimumSolderMaskSliver MinimumSolderMaskSliver_Baluns [All] p0 off: scope1count=1 scope1_0_kind=Board scope1_0_value=Board scope2count=1 scope2_0_kind=Board scope2_0_value=Board commentlength=76 // Protel DXP Scope 1 Expression Was: InComponent('T4')or InComponent('T5')
MinimumSolderMaskSliver [All] p0: scope1count=1 scope1_0_kind=Board scope1_0_value=Board scope2count=1 scope2_0_kind=Board scope2_0_value=Board commentlength=0
MinimumSolderMaskSliver MinimumSolderMaskSliver_Logo [All] p0: scope1count=1 scope1_0_kind=ComponentClass scope1_0_value=Logo scope2count=1 scope2_0_kind=ComponentClass scope2_0_value=Logo commentlength=0
MinimumSolderMaskSliver MinimumSolderMaskSliver_Baluns [InComponent('T4')or InComponent('T5')] p1: minsoldermaskwidth=0
MinimumSolderMaskSliver MinimumSolderMaskSliver_Logo [InComponentClass('Logo') vs InComponentClass('Logo')] p2: minsoldermaskwidth=0.7
MinimumSolderMaskSliver [All] p3: minsoldermaskwidth=3
NetAntennae [All] p0 off: scope1count=1 scope1_0_kind=Board scope1_0_value=Board scope2count=1 scope2_0_kind=Board scope2_0_value=Board commentlength=151 // Protel DXP Scope 1 Expression Was: Not((InNetClass('PWR1') or InNetClass('PWR2') or InNetClass('PWR3') or InNetClass('PWR4')) and ViaDiameter = 20)
NetAntennae [Not((InNetClass('PWR1') or InNetClass('PWR2') or InNetClass('PWR3') or InNetClass('PWR4')) and ViaDiameter = 20)] p1: netantennaetolerance=0
PasteMaskExpansion [All] p0: scope1count=1 scope1_0_kind=Board scope1_0_value=Board scope2count=1 scope2_0_kind=Board scope2_0_value=Board commentlength=0 expansion=0
PlaneClearance [All] p0: scope1count=1 scope1_0_kind=Board scope1_0_value=Board scope2count=1 scope2_0_kind=Board scope2_0_value=Board commentlength=0 clearance=20
PlaneConnect [All] p0: scope1count=1 scope1_0_kind=Board scope1_0_value=Board scope2count=1 scope2_0_kind=Board scope2_0_value=Board commentlength=0 planeconnectstyle=Relief reliefexpansion=10 reliefentries=4 reliefconductorwidth=10 reliefairgap=10
PlaneConnect [All] p1: planeconnectstyle=Relief reliefexpansion=10 reliefentries=4 reliefconductorwidth=10 reliefairgap=10
PolygonConnect [All] p0: scope1count=1 scope1_0_kind=Board scope1_0_value=Board scope2count=1 scope2_0_kind=Board scope2_0_value=Board commentlength=0 connectstyle=Relief reliefconductorwidth=25 reliefentries=4 polygonreliefangle="45 Angle"
PolygonConnect "FAN GND Probe Point" [All] p0 off: scope1count=1 scope1_0_kind=Board scope1_0_value=Board scope2count=1 scope2_0_kind=Board scope2_0_value=Board commentlength=178 connectstyle=Direct reliefconductorwidth=15 reliefentries=4 polygonreliefangle="90 Angle" // Protel DXP Scope 1 Expression Was: InComponent('PP2') or HasFootprint('Hirose_UX60SC-MB-5S8') or HasFootprint('HiRose-HK-LR-SR2-SWM1092-04A-MicroStirp-6mil-Female-Backdrill')
PolygonConnect "Thermal Pads Edge SMA" [All] p0 off: scope1count=1 scope1_0_kind=Board scope1_0_value=Board scope2count=1 scope2_0_kind=Board scope2_0_value=Board commentlength=62 connectstyle=Direct reliefconductorwidth=10 reliefentries=4 polygonreliefangle="90 Angle" // Protel DXP Scope 2 Expression Was: IsPad and HoleSize = 45
PolygonConnect "Thermal Pads" [All] p0 off: scope1count=1 scope1_0_kind=Board scope1_0_value=Board scope2count=1 scope2_0_kind=Board scope2_0_value=Board commentlength=63 connectstyle=Direct reliefconductorwidth=10 reliefentries=4 polygonreliefangle="90 Angle" // Protel DXP Scope 2 Expression Was: IsPad and HoleSize <= 39
PolygonConnect "FAN GND Probe Point" [InComponent('PP2') or HasFootprint('Hirose_UX60SC-MB-5S8') or HasFootprint('HiRose-HK-LR-SR2-SWM1092-04A-MicroStirp-6mil-Female-Backdrill')] p1: connectstyle=Direct reliefconductorwidth=15 reliefentries=4 polygonreliefangle="90 Angle" airgapwidth=15
PolygonConnect "Thermal Pads" [IsPolygon vs IsPad and HoleSize <= 39] p2: connectstyle=Direct reliefconductorwidth=10 reliefentries=4 polygonreliefangle="90 Angle" airgapwidth=10
PolygonConnect "Thermal Pads Edge SMA" [IsPolygon and OnLayer('L2 GND1') vs IsPad and HoleSize = 45] p3: connectstyle=Direct reliefconductorwidth=10 reliefentries=4 polygonreliefangle="90 Angle" airgapwidth=10
PolygonConnect [All] p4: thpad.connectstyle=Relief thpad.reliefconductorwidth=25 thpad.reliefentries=4 thpad.polygonreliefangle="45 Angle" thpad.airgapwidth=15 smdpad.connectstyle=Direct smdpad.reliefconductorwidth=10 smdpad.reliefentries=4 smdpad.polygonreliefangle="90 Angle" smdpad.airgapwidth=10 via.connectstyle=Direct via.reliefconductorwidth=10 via.reliefentries=4 via.polygonreliefangle="90 Angle" via.airgapwidth=10
RoutingCorners [All] p0: scope1count=1 scope1_0_kind=Board scope1_0_value=Board scope2count=1 scope2_0_kind=Board scope2_0_value=Board commentlength=0 cornerstyle=45-Degree minsetback=100 maxsetback=100
RoutingLayers [All] p0: scope1count=1 scope1_0_kind=Board scope1_0_value=Board scope2count=1 scope2_0_kind=Board scope2_0_value=Board commentlength=0 top layer=Automatic mid layer 1=Automatic mid layer 2=Automatic mid layer 3=Automatic mid layer 4=Automatic mid layer 5=Automatic mid layer 6=Automatic mid layer 7=Automatic mid layer 8=Automatic mid layer 9=Automatic mid layer 10=Automatic mid layer 11=Automatic mid layer 12=Automatic mid layer 13=Automatic mid layer 14=Automatic bottom layer=Automatic
RoutingPriority [All] p0: scope1count=1 scope1_0_kind=Board scope1_0_value=Board scope2count=1 scope2_0_kind=Board scope2_0_value=Board commentlength=0
RoutingTopology [All] p0: scope1count=1 scope1_0_kind=Board scope1_0_value=Board scope2count=1 scope2_0_kind=Board scope2_0_value=Board commentlength=0 topology=Shortest
RoutingVias [All] p0: scope1count=1 scope1_0_kind=Board scope1_0_value=Board scope2count=1 scope2_0_kind=Board scope2_0_value=Board commentlength=0 holewidth=16 width=34 viastyle="Through Hole" minholewidth=6 minwidth=16 maxholewidth=40 maxwidth=65
RoutingVias ThermalPadVias [All] p0 off: scope1count=1 scope1_0_kind=Board scope1_0_value=Board scope2count=1 scope2_0_kind=Board scope2_0_value=Board commentlength=63 holewidth=7.87 width=19.68 viastyle="Through Hole" minholewidth=6 minwidth=16 maxholewidth=65 maxwidth=65 // Protel DXP Scope 1 Expression Was: IsVia and InAnyComponent
RoutingVias ThermalPadVias [IsVia and InAnyComponent] p1: holewidth=7.87 width=19.68 viastyle="Through Hole" minholewidth=6 minwidth=16 maxholewidth=65 maxwidth=65
RoutingVias [All] p2: holewidth=16 width=34 viastyle="Through Hole" minholewidth=6 minwidth=16 maxholewidth=40 maxwidth=65
ShortCircuit [All] p0: scope1count=1 scope1_0_kind=Board scope1_0_value=Board scope2count=1 scope2_0_kind=Board scope2_0_value=Board commentlength=0 allowed=FALSE
SilkToBoardRegionClearance [All] p0 off: scope1count=1 scope1_0_kind=Board scope1_0_value=Board scope2count=1 scope2_0_kind=Board scope2_0_value=Board commentlength=130 // Protel DXP Scope 1 Expression Was: Not ((IsComment or IsDesignator) And (Hide <> 'False')) and not InRegion(1000,500,4000,800)
SilkToBoardRegionClearance [Not ((IsComment or IsDesignator) And (Hide <> 'False')) and not InRegion(1000,500,4000,800)] p1:
SilkToSilkClearance [All] p0: scope1count=1 scope1_0_kind=Board scope1_0_value=Board scope2count=1 scope2_0_kind=Board scope2_0_value=Board commentlength=0
SilkToSilkClearance SilkToSilkClearance_Pb-FreeLogo [All] p0 off: scope1count=1 scope1_0_kind=Board scope1_0_value=Board scope2count=1 scope2_0_kind=Board scope2_0_value=Board commentlength=120 // Protel DXP Scope 2 Expression Was: (HasFootprint('Pb-Free_Overlay_Medium') OR HasFootprint('Pb-Free_Overlay_Small'))
SilkToSilkClearance SilkToSilkClearance_Pb-FreeLogo [(HasFootprint('Pb-Free_Overlay_Medium') OR HasFootprint('Pb-Free_Overlay_Small')) vs (HasFootprint('Pb-Free_Overlay_Medium') OR HasFootprint('Pb-Free_Overlay_Small'))] p1: silktosilkclearance=0
SilkToSilkClearance [All] p2: silktosilkclearance=0
SilkToSolderMaskClearance "Silk to Solder Mask Opening" [All] p0: scope1count=1 scope1_0_kind=Board scope1_0_value=Board scope2count=1 scope2_0_kind=Board scope2_0_value=Board commentlength=0
SilkToSolderMaskClearance SilkToComponentPadClearance [All] p0 off: scope1count=1 scope1_0_kind=Board scope1_0_value=Board scope2count=1 scope2_0_kind=Board scope2_0_value=Board commentlength=87 // Protel DXP Scope 1 Expression Was: (IsPad or IsFill or IsRegion) and InAnycomponent
SilkToSolderMaskClearance SilkToComponentPadClearance [(IsPad or IsFill or IsRegion) and InAnycomponent] p1: minsilkscreentomaskgap=0 clearancetoexposedcopper=TRUE
SilkToSolderMaskClearance "Silk to Solder Mask Opening" [All] p2: minsilkscreentomaskgap=0 clearancetoexposedcopper=FALSE
SolderMaskExpansion [All] p0: scope1count=1 scope1_0_kind=Board scope1_0_value=Board scope2count=1 scope2_0_kind=Board scope2_0_value=Board commentlength=0 expansion=1.97
SolderMaskExpansion [All] p1: expansion=1.97 istentingtop=FALSE
SupplyNets "Schematic Supply Nets_25" [All] p0: scope1count=1 scope1_0_kind=Net scope1_0_value=VDDSYS18 scope2count=1 scope2_0_kind=Board scope2_0_value=Board commentlength=0 voltage=0.000
SupplyNets "Schematic Supply Nets_24" [All] p0: scope1count=1 scope1_0_kind=Net scope1_0_value=5V_Utility scope2count=1 scope2_0_kind=Board scope2_0_value=Board commentlength=0 voltage=0.000
SupplyNets "Schematic Supply Nets_23" [All] p0: scope1count=1 scope1_0_kind=Net scope1_0_value=VDDLB scope2count=1 scope2_0_kind=Board scope2_0_value=Board commentlength=0 voltage=0.000
SupplyNets "Schematic Supply Nets_22" [All] p0: scope1count=1 scope1_0_kind=Net scope1_0_value=3p3V_EEPROM scope2count=1 scope2_0_kind=Board scope2_0_value=Board commentlength=0 voltage=0.000
SupplyNets "Schematic Supply Nets_21" [All] p0: scope1count=1 scope1_0_kind=Net scope1_0_value=VDD_FPGA scope2count=1 scope2_0_kind=Board scope2_0_value=Board commentlength=0 voltage=0.000
SupplyNets "Schematic Supply Nets_20" [All] p0: scope1count=1 scope1_0_kind=Net scope1_0_value=GND scope2count=1 scope2_0_kind=Board scope2_0_value=Board commentlength=0 voltage=0.000
SupplyNets "Schematic Supply Nets_19" [All] p0: scope1count=1 scope1_0_kind=Net scope1_0_value=VDDLA scope2count=1 scope2_0_kind=Board scope2_0_value=Board commentlength=0 voltage=0.000
SupplyNets "Schematic Supply Nets_18" [All] p0: scope1count=1 scope1_0_kind=Net scope1_0_value=VDDA18A scope2count=1 scope2_0_kind=Board scope2_0_value=Board commentlength=0 voltage=0.000
SupplyNets "Schematic Supply Nets_17" [All] p0: scope1count=1 scope1_0_kind=Net scope1_0_value=3P3VAUX-FMC scope2count=1 scope2_0_kind=Board scope2_0_value=Board commentlength=0 voltage=0.000
SupplyNets "Schematic Supply Nets_16" [All] p0: scope1count=1 scope1_0_kind=Net scope1_0_value=VDDIO scope2count=1 scope2_0_kind=Board scope2_0_value=Board commentlength=0 voltage=0.000
SupplyNets "Schematic Supply Nets_15" [All] p0: scope1count=1 scope1_0_kind=Net scope1_0_value=12V_FMC scope2count=1 scope2_0_kind=Board scope2_0_value=Board commentlength=0 voltage=0.000
SupplyNets "Schematic Supply Nets_14" [All] p0: scope1count=1 scope1_0_kind=Net scope1_0_value=3p3_FMC scope2count=1 scope2_0_kind=Board scope2_0_value=Board commentlength=0 voltage=0.000
SupplyNets "Schematic Supply Nets_13" [All] p0: scope1count=1 scope1_0_kind=Net scope1_0_value=2p3V_Analog_LDO scope2count=1 scope2_0_kind=Board scope2_0_value=Board commentlength=0 voltage=0.000
SupplyNets "Schematic Supply Nets_12" [All] p0: scope1count=1 scope1_0_kind=Net scope1_0_value=VDDL scope2count=1 scope2_0_kind=Board scope2_0_value=Board commentlength=0 voltage=0.000
SupplyNets "Schematic Supply Nets_11" [All] p0: scope1count=1 scope1_0_kind=Net scope1_0_value=3p3V_Utility scope2count=1 scope2_0_kind=Board scope2_0_value=Board commentlength=0 voltage=0.000
SupplyNets "Schematic Supply Nets_10" [All] p0: scope1count=1 scope1_0_kind=Net scope1_0_value=VDDR scope2count=1 scope2_0_kind=Board scope2_0_value=Board commentlength=0 voltage=0.000
SupplyNets "Schematic Supply Nets_9" [All] p0: scope1count=1 scope1_0_kind=Net scope1_0_value=3p3V_Clock scope2count=1 scope2_0_kind=Board scope2_0_value=Board commentlength=0 voltage=0.000
SupplyNets "Schematic Supply Nets_8" [All] p0: scope1count=1 scope1_0_kind=Net scope1_0_value=VADJ_FMC scope2count=1 scope2_0_kind=Board scope2_0_value=Board commentlength=0 voltage=0.000
SupplyNets "Schematic Supply Nets_7" [All] p0: scope1count=1 scope1_0_kind=Net scope1_0_value=VEExA scope2count=1 scope2_0_kind=Board scope2_0_value=Board commentlength=0 voltage=0.000
SupplyNets "Schematic Supply Nets_6" [All] p0: scope1count=1 scope1_0_kind=Net scope1_0_value=VDDCLK10 scope2count=1 scope2_0_kind=Board scope2_0_value=Board commentlength=0 voltage=0.000
SupplyNets "Schematic Supply Nets_5" [All] p0: scope1count=1 scope1_0_kind=Net scope1_0_value=VEExB scope2count=1 scope2_0_kind=Board scope2_0_value=Board commentlength=0 voltage=0.000
SupplyNets "Schematic Supply Nets_4" [All] p0: scope1count=1 scope1_0_kind=Net scope1_0_value=DVDD scope2count=1 scope2_0_kind=Board scope2_0_value=Board commentlength=0 voltage=0.000
SupplyNets "Schematic Supply Nets_3" [All] p0: scope1count=1 scope1_0_kind=Net scope1_0_value=VDDCLK18 scope2count=1 scope2_0_kind=Board scope2_0_value=Board commentlength=0 voltage=0.000
SupplyNets "Schematic Supply Nets_2" [All] p0: scope1count=1 scope1_0_kind=Net scope1_0_value=VDDA18B scope2count=1 scope2_0_kind=Board scope2_0_value=Board commentlength=0 voltage=0.000
SupplyNets "Schematic Supply Nets_1" [All] p0: scope1count=1 scope1_0_kind=Net scope1_0_value=VDDA scope2count=1 scope2_0_kind=Board scope2_0_value=Board commentlength=0 voltage=0.000
SupplyNets "Schematic Supply Nets" [All] p0: scope1count=1 scope1_0_kind=Net scope1_0_value=12V scope2count=1 scope2_0_kind=Board scope2_0_value=Board commentlength=0 voltage=0.000
SupplyNets "Schematic Supply Nets_25" [InNet('VDDSYS18')] p1: voltage=0.000
SupplyNets "Schematic Supply Nets_24" [InNet('5V_Utility')] p2: voltage=0.000
SupplyNets "Schematic Supply Nets_23" [InNet('VDDLB')] p3: voltage=0.000
SupplyNets "Schematic Supply Nets_22" [InNet('3p3V_EEPROM')] p4: voltage=0.000
SupplyNets "Schematic Supply Nets_21" [InNet('VDD_FPGA')] p5: voltage=0.000
SupplyNets "Schematic Supply Nets_20" [InNet('GND')] p6: voltage=0.000
SupplyNets "Schematic Supply Nets_19" [InNet('VDDLA')] p7: voltage=0.000
SupplyNets "Schematic Supply Nets_18" [InNet('VDDA18A')] p8: voltage=0.000
SupplyNets "Schematic Supply Nets_17" [InNet('3P3VAUX-FMC')] p9: voltage=0.000
SupplyNets "Schematic Supply Nets_16" [InNet('VDDIO')] p10: voltage=0.000
SupplyNets "Schematic Supply Nets_15" [InNet('12V_FMC')] p11: voltage=0.000
SupplyNets "Schematic Supply Nets_14" [InNet('3p3_FMC')] p12: voltage=0.000
SupplyNets "Schematic Supply Nets_13" [InNet('2p3V_Analog_LDO')] p13: voltage=0.000
SupplyNets "Schematic Supply Nets_12" [InNet('VDDL')] p14: voltage=0.000
SupplyNets "Schematic Supply Nets_11" [InNet('3p3V_Utility')] p15: voltage=0.000
SupplyNets "Schematic Supply Nets_10" [InNet('VDDR')] p16: voltage=0.000
SupplyNets "Schematic Supply Nets_9" [InNet('3p3V_Clock')] p17: voltage=0.000
SupplyNets "Schematic Supply Nets_8" [InNet('VADJ_FMC')] p18: voltage=0.000
SupplyNets "Schematic Supply Nets_7" [InNet('VEExA')] p19: voltage=0.000
SupplyNets "Schematic Supply Nets_6" [InNet('VDDCLK10')] p20: voltage=0.000
SupplyNets "Schematic Supply Nets_5" [InNet('VEExB')] p21: voltage=0.000
SupplyNets "Schematic Supply Nets_4" [InNet('DVDD')] p22: voltage=0.000
SupplyNets "Schematic Supply Nets_3" [InNet('VDDCLK18')] p23: voltage=0.000
SupplyNets "Schematic Supply Nets_2" [InNet('VDDA18B')] p24: voltage=0.000
SupplyNets "Schematic Supply Nets_1" [InNet('VDDA')] p25: voltage=0.000
SupplyNets "Schematic Supply Nets" [InNet('12V')] p26: voltage=0.000
UnRoutedNet [All] p0: scope1count=1 scope1_0_kind=Board scope1_0_value=Board scope2count=1 scope2_0_kind=Board scope2_0_value=Board commentlength=0
UnRoutedNet [All] p1: checkbadconnections=TRUE
UnpouredPolygon [All] p0: scope1count=1 scope1_0_kind=Board scope1_0_value=Board scope2count=1 scope2_0_kind=Board scope2_0_value=Board commentlength=0
Width Width_InPolygon [All] p0 off: scope1count=1 scope1_0_kind=Board scope1_0_value=Board scope2count=1 scope2_0_kind=Board scope2_0_value=Board commentlength=106 maxlimit=10000 minlimit=0 preferedwidth=0 // Protel DXP Scope 1 Expression Was: InNet('GND') OR InNet('3p3V') OR InNet('1p8V') OR InNet('LMX_2p5V')
Width [All] p0: scope1count=1 scope1_0_kind=Board scope1_0_value=Board scope2count=1 scope2_0_kind=Board scope2_0_value=Board commentlength=0 maxlimit=100 minlimit=4 preferedwidth=12.3
Width Width_InPolygon [InNet('GND') OR InNet('3p3V') OR InNet('1p8V') OR InNet('LMX_2p5V')] p1: maxlimit=10000 minlimit=0 preferedwidth=0 checkconnectedcopper=TRUE
Width [All] p2: maxlimit=100 minlimit=4 preferedwidth=12.3 checkconnectedcopper=TRUE
12 further rules are at their usual default settings.

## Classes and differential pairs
component class "FPGA to DUT Control": C20 C34 C84 C108 PP52 PP53 U20 U39
net class LMK_Clocks: DAC_SYSREF_LMK_N DAC_SYSREF_LMK_P FPGA_CORECLK_n FPGA_CORECLK_p FPGA_SYSREF_n FPGA_SYSREF_p GBTCLK0_FMC_n GBTCLK0_FMC_p GBTCLK1_FMC_n GBTCLK1_FMC_p LMK_DCLKOUT4_N LMK_DCLKOUT4_P LMK_DCLKOUT6_N LMK_DCLKOUT6_P LMK_DCLKOUT10_N LMK_DCLKOUT10_P LMK_SDCLKOUT1_N LMK_SDCLKOUT1_P LMK_SDCLKOUT11_N LMK_SDCLKOUT11_P
net class LMXK: 3p3V_Clock
net class I2C: FMC_I2C_SCL FMC_I2C_SDA SCL_I2C SDA_I2C USB_I2C_SCL USB_I2C_SDAr
component class "DC-DC DAC Digital": C43 C86 C87 C88 C89 C90 C91 C92 C93 C94 C95 C96 D5 L1 PP17 R83 R84 R85 R86 R87 R88 R89 R90 R191 U18 U19 U33
component class "DAC39RF12 IO": C99 C100 C101 C102 C103 C104 C105 C170 C171 C172 J6 J11 J12 J13 PP40 PP41 PP42 PP43 R107 R108 R109 R110 R143 R144 R145 R146 R147 R148 R149 R150 R192 R193 R194 SW3 T9 U34 U38
component class "Comms FTDI-Board_I2C": C39 C69 C70 C97 C98 C146 C147 C148 C149 C150 C151 C152 C153 C154 C155 C158 C159 C160 FB7 FB8 J9 PP19 PP20 PP44 PP45 PP46 PP47 PP54 PP55 PP56 PP57 R44 R62 R111 R114 R115 R116 R117 R118 R119 R120 R121 R122 R123 R124 R125 R126 R127 R128 R129 R130 R131 R132 R138 R139 R157 R170 U5 U21 U24 U25 U26 U27 U28 Y1
component class Hardware: !PCB FanNotes1 FH1 FID1 FID2 FID3 H1 H2 H3 H4 H5 H6 H7 H8 LBL1 Logo1 LOGO2 Logo3 LOGO4 Logo5 LOGO6 Logo7 MP1 MP5 ZZ1
component class "FMC+ Sections J - Z": J10 R92 R93 R94 R96 R97 R98 R99 R100 R178 R179 R180 R181
component class "FMC+ Sections A-H": C73 C245 D4 PP25 PP30 PP33 PP34 PP48 PP49 PP50 PP51 R95 R151 R152 R153 R154 R155 R156 R158 R159 R160 R161 R162 R163 R164 R165 R166 R167 R168 R169 R171 R172 R173 R174 R175 R176 R177 U23 U40
component class "DC-DC Analog": C19 C23 C24 C25 C26 C27 C29 C30 C33 C35 C36 C37 C38 C41 FB1 FB2 FC3 PP3 PP4 R36 R39 R40 R41 R42 R46 R47 R48 R49 R50 U6 U8
component class "DAC LDO N1p8V": C55 C56 C57 C58 C59 C63 C64 C65 C66 C67 C71 FC7 FC8 PP11 PP12 R58 R59 R60 R61 R64 R65 R66 U11 U12 U13
component class "DAC LDO 1p8V": C42 C44 C45 C46 C48 C49 C50 C51 C53 C54 FB3 FB4 FC5 PP5 PP6 PP7 PP8 PP9 PP10 PP35 R51 R52 R53 R54 R55 R56 R57 U9 U10
component class "DAC LDO 1p0V": C40 C47 C72 C74 C75 C76 C78 C79 C80 C82 C83 C85 C109 C110 C111 FB5 FB6 FC10 PP13 PP14 PP15 PP16 R67 R68 R69 R70 R71 R72 R73 R74 R75 R76 R77 R79 R80 R81 R82 U14 U15 U16 U17
component class "DAC39RF12 Power": C173 C174 C175 C176 C177 C178 C179 C180 C181 C182 C183 C184 C185 C186 C187 C188 C189 C190 C191 C192 C193 C194 C195 C196 C197 C198 C199 C200 C201 C202 C203 C204 C205 C206 C207 C208 C209 C210 C211 C212 C213 C214 C215 C216 C217 C218 C219 C220 C221 C222 C223 C224 C225 C226 C227 C228 C229 C230 C231 C232 C233 C234 C235 C236 C237 C238 C239 C240 C241 C242 C243 C244 U1
component class "DAC39RF12 Outputs": C1 C2 C3 C4 C5 C6 C16 C17 C18 C21 C22 C28 C52 C60 C61 C62 J1 J2 J3 J4 R1 R2 R3 R4 R5 R6 R7 R8 R9 R10 R11 R12 R13 R14 R15 R16 R17 R18 R19 R20 T1 T2 T3 T4 T5 T6 T7 T8
component class "Comms SPI MUX & LVL Translate": C68 C161 C162 C163 C164 C165 C167 C168 C169 PP21 PP22 PP23 PP24 PP26 PP27 PP28 PP29 PP31 PP32 PP36 PP37 PP38 PP39 R27 R45 R63 R78 R133 R134 R135 R136 R137 R140 R141 R142 R182 R183 R184 R185 R186 R187 R188 R189 R190 SW2 SW4 U7 U29 U30 U31 U32 U35 U36 U37
component class "Clocking LMK04828": C31 C32 C77 C81 C106 C107 C115 C116 C117 C118 C119 C120 C121 C122 C123 C124 C125 C126 C127 C128 C131 C132 C133 C134 C137 C138 C139 C140 C144 C145 J7 J8 J14 PP18 R34 R35 R37 R38 R43 R91 R101 R102 R103 R104 R105 R106 R112 R113 U22
component class "12V Input": C7 C8 C9 C10 C11 C12 C13 C14 C15 D1 D2 D3 F1 F2 J5 PP1 PP2 Q1 R21 R22 R23 R24 R25 R26 R28 R29 R30 R31 R32 R33 SW1 TP1 TP2 TP3 TP4 TP5 U2 U3 U4
net class GenPwr: 3p3V_Utility 5V_Utility 12V 12V_FMC VADJ_FMC VDD_FPGA
net class PWR4: VDDIO VDDR VDDSYS18
net class PWR3: VDDA18A VDDA18B VDDCLK18 VEExA VEExB
net class PWR2: VDDCLK10 VDDLA VDDLB
net class PWR1: DVDD
net class Power: 3p3V_Clock 3p3V_Utility 5V_Utility 12V 12V_FMC DVDD VADJ_FMC VDD_FPGA VDDA18A VDDA18B VDDCLK10 VDDCLK18 VDDIO VDDLA VDDLB VDDR VDDSYS18 VEExA VEExB
net class serdes: 0SRX_n 0SRX_p 1SRX_n 1SRX_p 2SRX_n 2SRX_p 3SRX_n 3SRX_p 4SRX_n 4SRX_p 5SRX_n 5SRX_p 6SRX_n 6SRX_p 7SRX_n 7SRX_p 8SRX_n 8SRX_p 9SRX_n 9SRX_p 10SRX_n 10SRX_p 11SRX_n 11SRX_p 12SRX_n 12SRX_p 13SRX_n 13SRX_p 14SRX_n 14SRX_p 15SRX_n 15SRX_p
differential pair LMK_SDCLKOUT1: +LMK_SDCLKOUT1_P -LMK_SDCLKOUT1_N
differential pair DAC_SYSREF_LMK: +DAC_SYSREF_LMK_P -DAC_SYSREF_LMK_N
differential pair DP21_M2C: +DP21_M2C_P -DP21_M2C_N
differential pair DP20_M2C: +DP20_M2C_P -DP20_M2C_N
differential pair DP15_M2C: +DP15_M2C_P -DP15_M2C_N
differential pair DP14_M2C: +DP14_M2C_P -DP14_M2C_N
differential pair LMK_SDCLKOUT11: +LMK_SDCLKOUT11_P -LMK_SDCLKOUT11_N
differential pair LMK_DCLKOUT10: +LMK_DCLKOUT10_P -LMK_DCLKOUT10_N
differential pair LMK_DCLKOUT6: +LMK_DCLKOUT6_P -LMK_DCLKOUT6_N
differential pair LMK_DCLKOUT4: +LMK_DCLKOUT4_P -LMK_DCLKOUT4_N
differential pair GBTCLK1_FMC: +GBTCLK1_FMC_p -GBTCLK1_FMC_n
differential pair GBTCLK0_FMC: +GBTCLK0_FMC_p -GBTCLK0_FMC_n
differential pair FPGA_SYSREF: +FPGA_SYSREF_p -FPGA_SYSREF_n
differential pair FPGA_CORECLK: +FPGA_CORECLK_p -FPGA_CORECLK_n
differential pair 15SRX: +15SRX_p -15SRX_n
differential pair 14SRX: +14SRX_p -14SRX_n
differential pair 13SRX: +13SRX_p -13SRX_n
differential pair 12SRX: +12SRX_p -12SRX_n
differential pair 11SRX: +11SRX_p -11SRX_n
differential pair 10SRX: +10SRX_p -10SRX_n
differential pair 9SRX: +9SRX_p -9SRX_n
differential pair 8SRX: +8SRX_p -8SRX_n
differential pair 7SRX: +7SRX_p -7SRX_n
differential pair 6SRX: +6SRX_p -6SRX_n
differential pair 5SRX: +5SRX_p -5SRX_n
differential pair 4SRX: +4SRX_p -4SRX_n
differential pair 3SRX: +3SRX_p -3SRX_n
differential pair 2SRX: +2SRX_p -2SRX_n
differential pair 1SRX: +1SRX_p -1SRX_n
differential pair " ": +0SRX_p -0SRX_n

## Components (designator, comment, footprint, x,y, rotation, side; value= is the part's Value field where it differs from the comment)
C1 "0201BB104KW160" 0201_cap#1 3257.61,557.43 r90 top
C2 "0201BB104KW160" 0201_cap#1 3471.58,214.04 r180 top
C3 "0201BB104KW160" 0201_cap#1 3157.6,557.43 r90 top
C4 "0201BB104KW160" 0201_cap#1 3257.61,2158.14 r270 top
C5 "0201BB104KW160" 0201_cap#1 3471.58,2501.53 r180 top
C6 "0201BB104KW160" 0201_cap#1 3157.6,2158.14 r270 top
C7 "C2012X7R1H105K125AB" 0805L_cap 1001.89,287.2 r0 bottom
C8 "C2012X7R1H105K125AB" 0805L_cap 1480.24,392.03 r270 bottom
C9 "C2012X7R1H105K125AB" 0805L_cap 1465.24,287.97 r90 bottom
C10 "CGA3E2X7R1H102K080AA" 0603L_cap#1 1250,217.44 r90 bottom
C11 "CGA3E2X7R1H102K080AA" 0603L_cap#1 1300,198.66 r90 bottom
C12 "08053D106KAT4A" 0805L_cap 299.83,1760.42 r180 bottom
C13 "C1005X5R1A475K050BE" 0402L_cap 280.15,1583.65 r180 bottom
C14 "08053D106KAT4A" 0805L_cap 299.83,1410.42 r180 bottom
C15 "C1005X5R1A475K050BE" 0402L_cap 280.15,1233.65 r180 bottom
C16 "GJM0335C1HR50WB01D" 0201_cap#1 3398.98,499.43 r180 bottom
C17 "0201BB104KW160" 0201_cap#1 3493.62,214.04 r0 top
C18 "GJM0335C1HR50WB01D" 0201_cap#1 3321.02,499.43 r0 bottom
C19 "GRM188R61E106KA73J" 0603L_cap#1 1087.65,2580 r180 top
C20 "GRM155R61E104KA87D" 0402L#1 590.45,1262.88 r180 top
C21 "GJM0335C1HR50WB01D" 0201_cap#1 3397.14,2216.15 r180 bottom
C22 "0201BB104KW160" 0201_cap#1 3493.63,2501.53 r0 top
C23 "C2012X7S1A226M125AC" 0805L_cap 1278,2434.53 r90 top
C24 "C2012X7S1A226M125AC" 0805L_cap 1347.32,2434.53 r90 top
C25 "C2012X7S1A226M125AC" 0805L_cap 1278,2558.54 r270 top
C26 "C2012X7S1A226M125AC" 0805L_cap 1426.06,2434.53 r90 top
C27 "CGA2B1X5R1C224M050BC" 0402L_cap 939.44,2495.63 r0 top
C28 "GJM0335C1HR50WB01D" 0201_cap#1 3318.28,2216.02 r0 bottom
C29 "GRM188R61E106KA73J" 0603L_cap#1 1087.65,2630 r180 top
C30 "GRM188R61E106KA73J" 0603L_cap#1 273.29,1000.35 r180 top
C31 "GRM033Z71C104KE14D" 0201_cap#2 2032.96,2530.98 r0 top
C32 "GRM033Z71C104KE14D" 0201_cap#2 2165.17,2530.98 r180 top
C33 "GRM188R61E106KA73J" 0603L_cap#1 273.29,1050.35 r180 top
C34 "GRM155R61E104KA87D" 0402L#1 590.45,1065.84 r180 top
C35 "C2012X7S1A226M125AC" 0805L_cap 463.65,854.88 r90 top
C36 "C2012X7S1A226M125AC" 0805L_cap 532.96,854.88 r90 top
C37 "C2012X7S1A226M125AC" 0805L_cap 463.65,978.9 r270 top
C38 "C2012X7S1A226M125AC" 0805L_cap 611.7,854.88 r90 top
C39 "CGA3E1X5R1A335K080AC" 0603L_cap#1 815.28,2402.53 r270 bottom
C40 "C2012X7S1A226M125AC" 0805L_cap 854.64,936.71 r270 top
C41 "CGA2B1X5R1C224M050BC" 0402L_cap 125.08,915.98 r0 top
C42 "GRM155R61E104KA87D" 0402L#1 1247.95,1074.87 r270 bottom
C43 "GRM0335C1H820JA01D" 0201_cap#1 1280.62,1976.49 r270 top
C44 "NFM18PC105R0J3D" NFM18PC 1673.37,1233.43 r0 top
C45 "0603ZD106KAT2A" 0603L_cap#1 1053.11,1176.73 r270 top
C46 "C1005X5R1E105K050BC" 0402L_cap 1293.13,1205.86 r270 top
C47 "C2012X7S1A226M125AC" 0805L_cap 758.96,720.09 r0 top
C48 "NFM18PC105R0J3D" NFM18PC 1673.37,1283.43 r0 top
C49 "C1005X5R1A475K050BE" 0402L_cap 1047.11,1072.01 r90 top
C50 "C2012X7S1A226M125AC" 0805L_cap 750.88,1134.75 r0 top
C51 "NFM18PC105R0J3D" NFM18PC 1673.37,1133.43 r0 top
C52 "0201BB104KW160" 0201_cap#1 3246.58,568.46 r0 top
C53 "NFM18PC105R0J3D" NFM18PC 1766.36,1071.46 r0 top
C54 "NFM18PC105R0J3D" NFM18PC 1673.37,1183.43 r0 top
C55 "GRM155R61E104KA87D" 0402L#1 1023.63,1457.01 r0 bottom
C56 "0603ZD106KAT2A" 0603L_cap#1 1224.34,1571.17 r90 top
C57 "C1005X5R1A225K050BC" 0402L_cap 1179.34,1575.11 r90 top
C58 "GRM033R61A105ME44D" 0201_cap#1 1035.54,1604.63 r90 top
C59 "0603ZD106KAT2A" 0603L_cap#1 1213.79,1694.67 r180 top
C60 "0201BB104KW160" 0201_cap#1 3168.62,568.59 r180 top
C61 "0201BB104KW160" 0201_cap#1 3247.24,2147.12 r0 top
C62 "0201BB104KW160" 0201_cap#1 3167.96,2147.12 r180 top
C63 "0603ZD106KAT2A" 0603L_cap#1 1212.8,1644.99 r180 top
C64 "0603ZD106KAT2A" 0603L_cap#1 1488.96,1751.27 r270 top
